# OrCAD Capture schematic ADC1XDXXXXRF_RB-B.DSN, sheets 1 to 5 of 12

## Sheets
1 Title Page
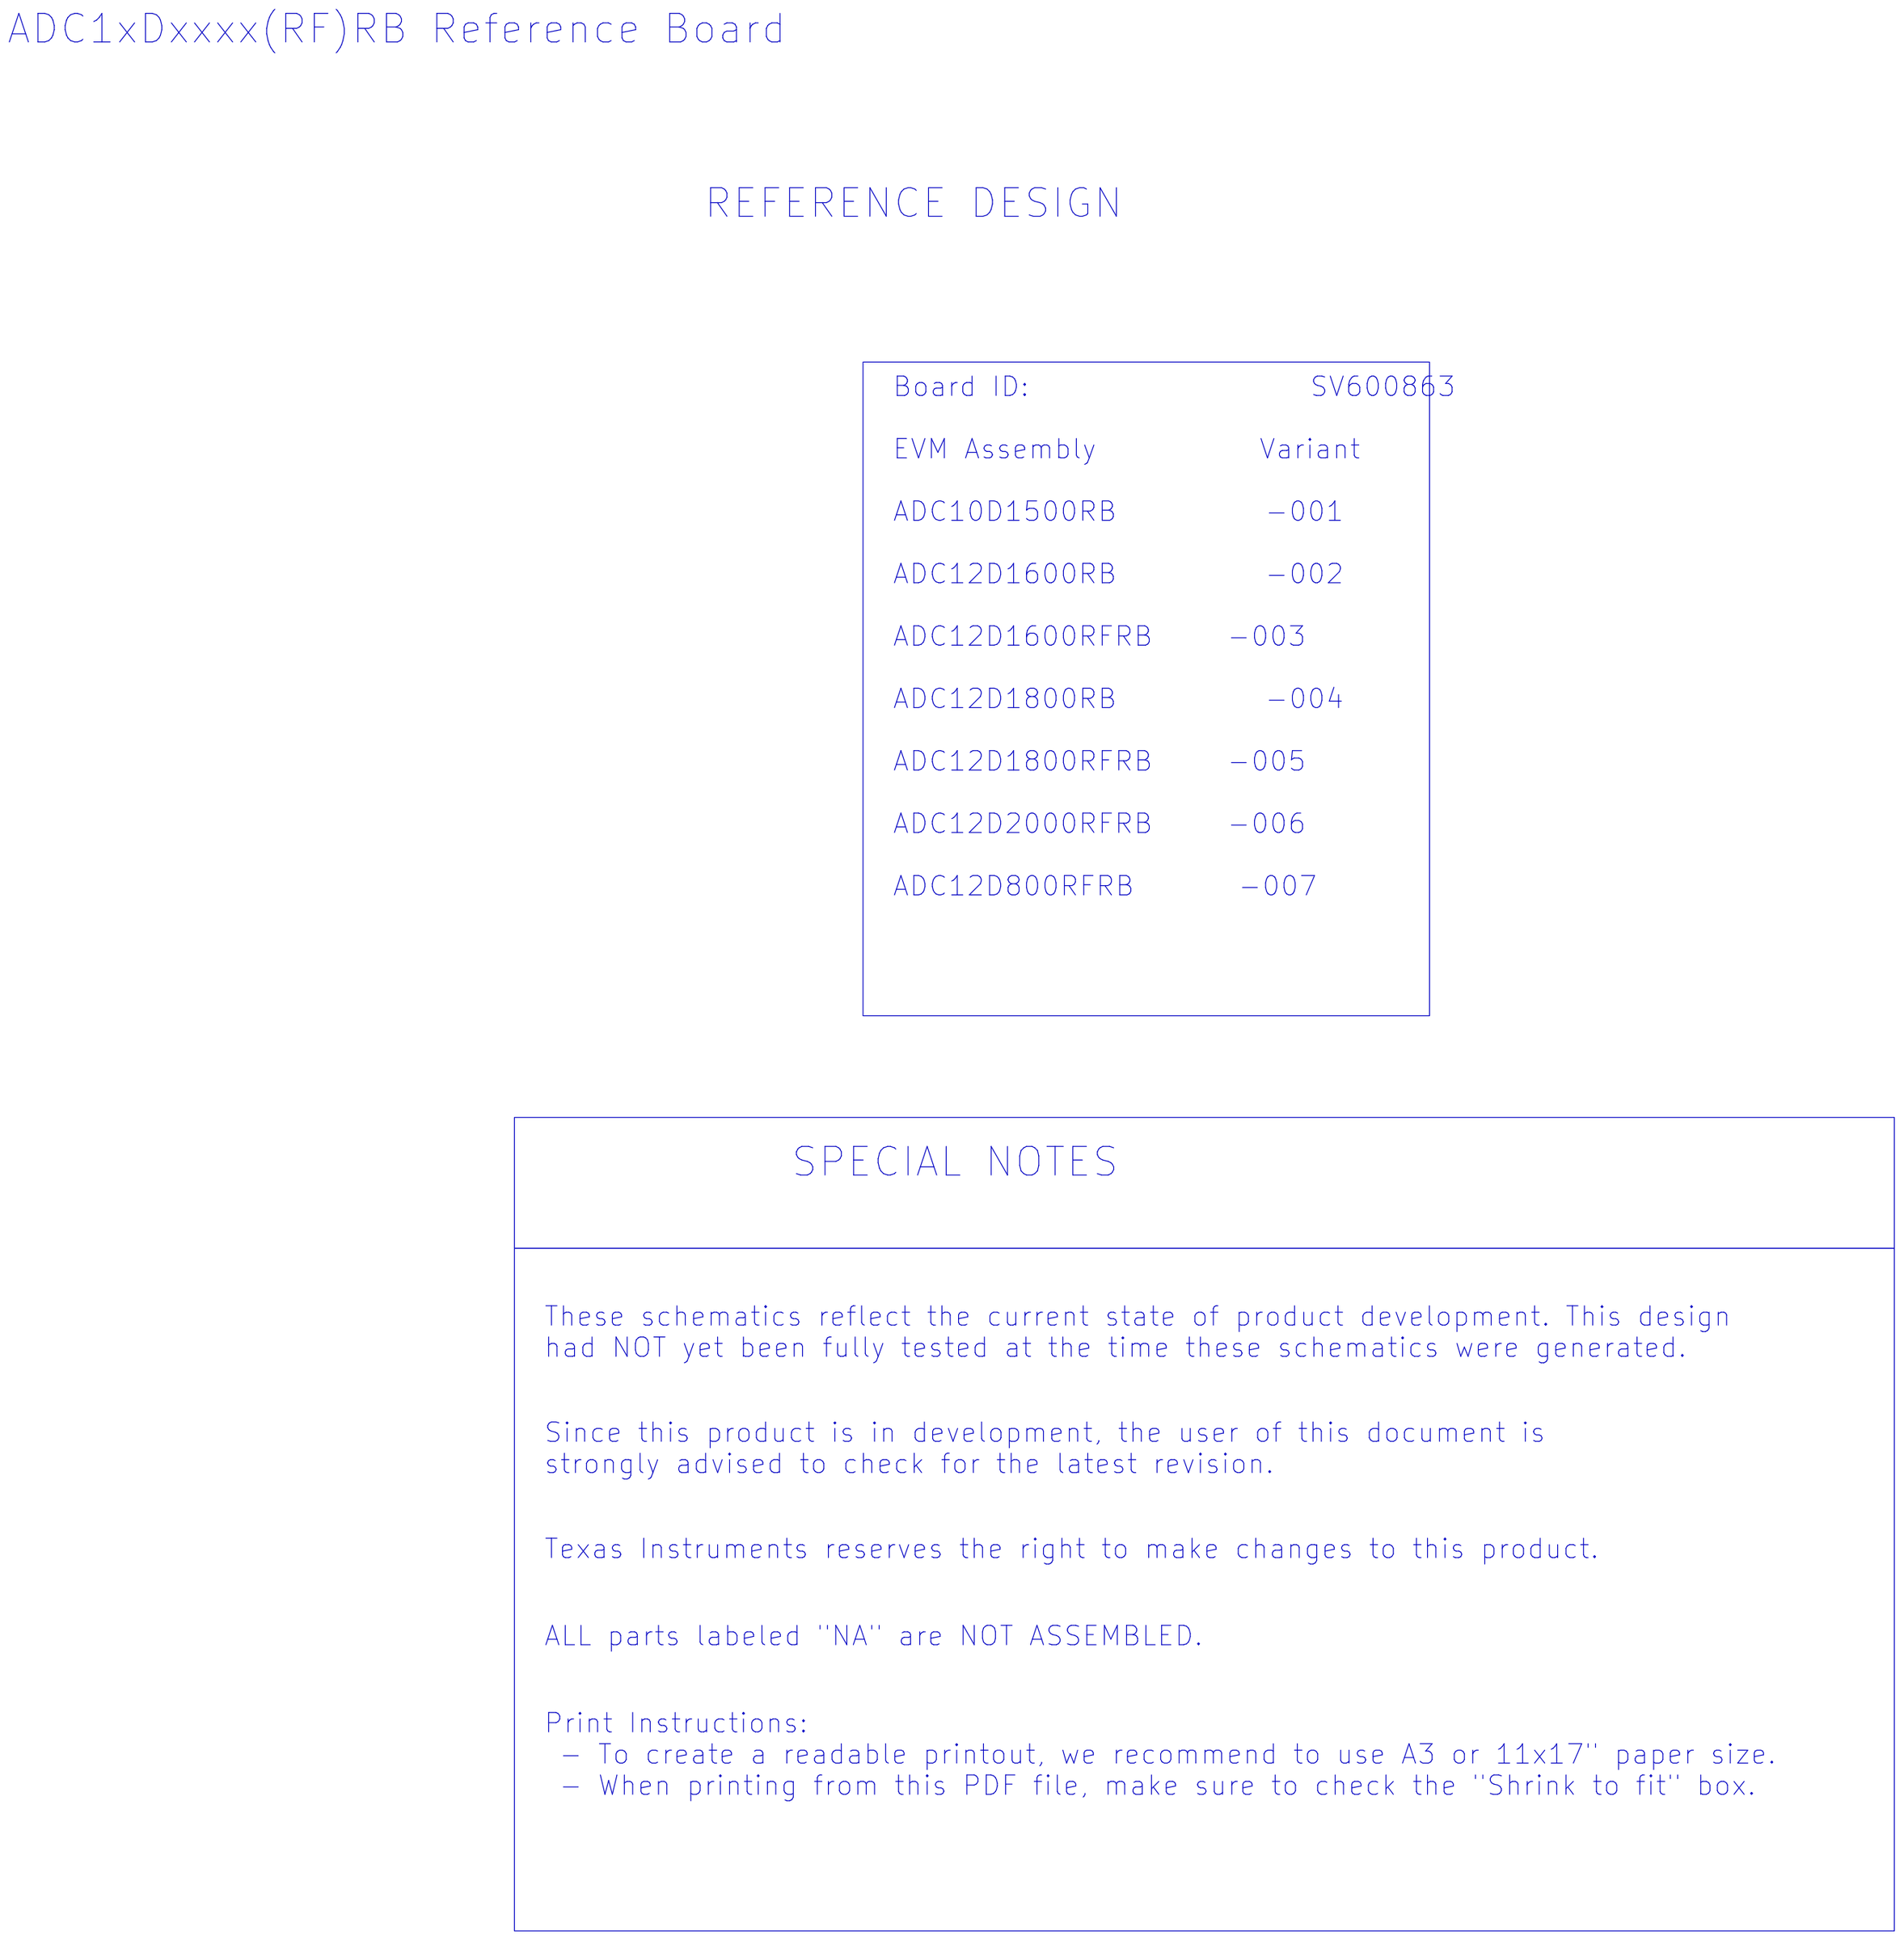
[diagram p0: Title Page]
2 TopBlock: size C
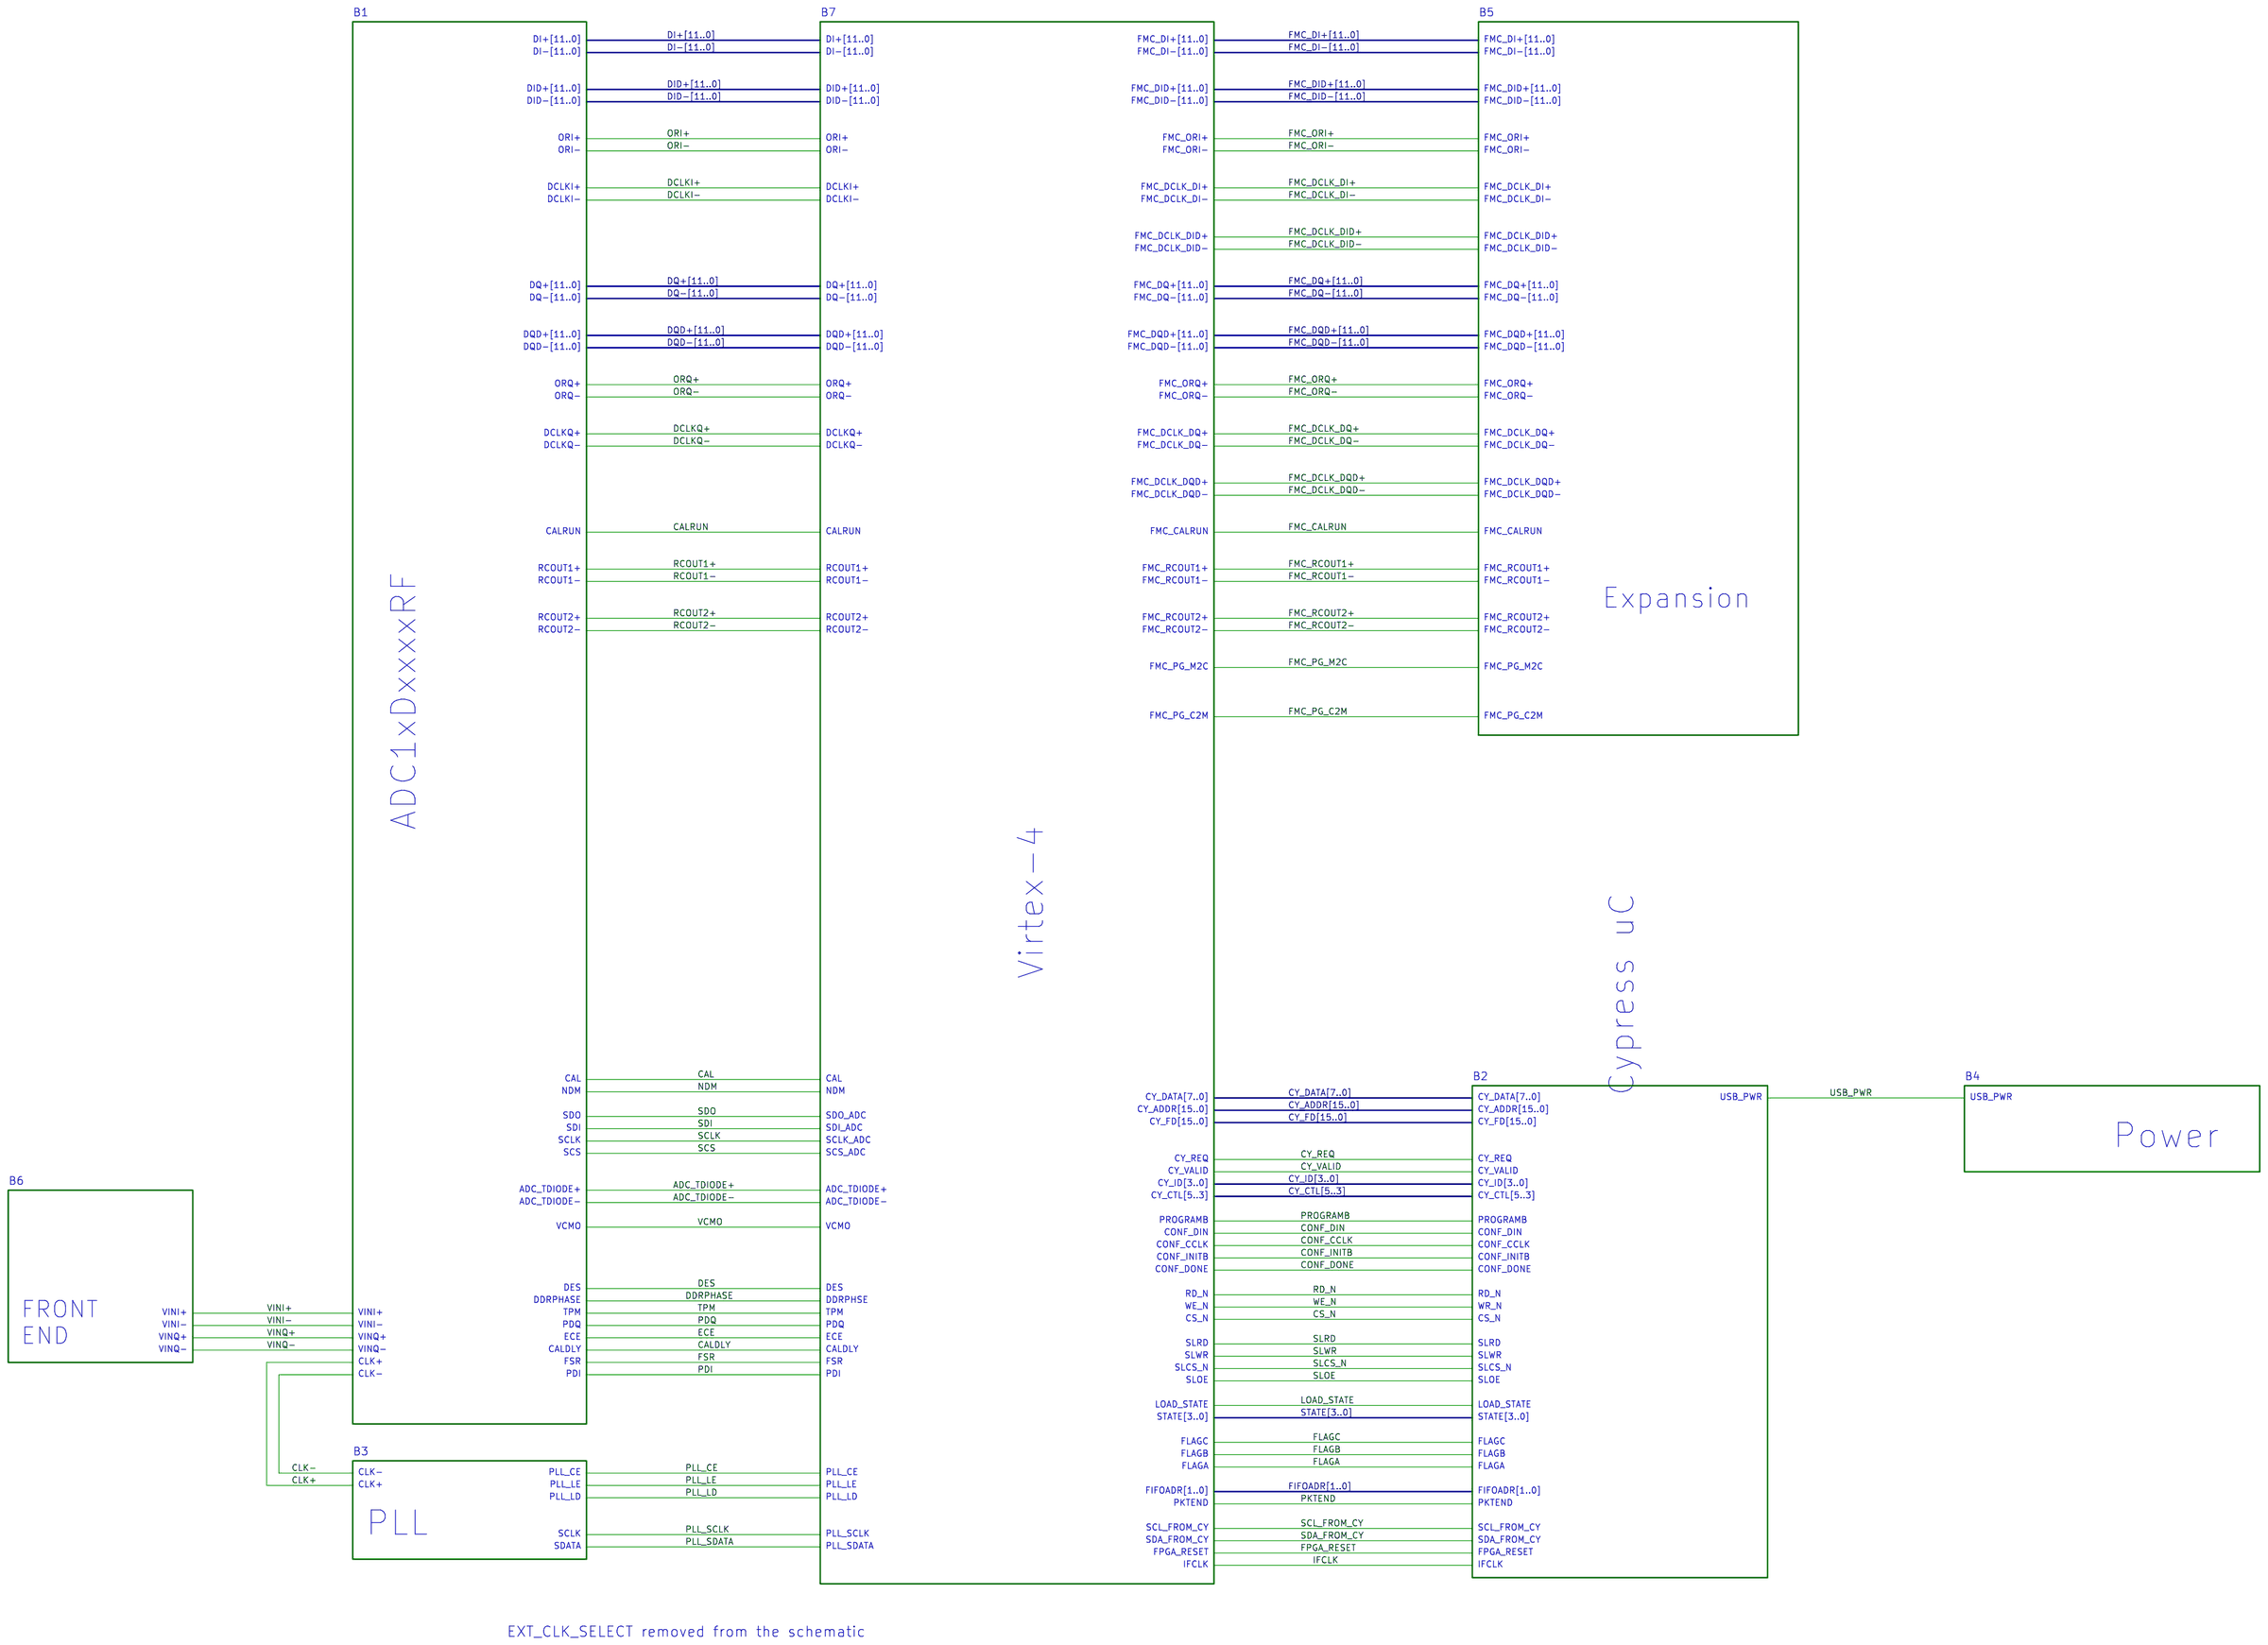
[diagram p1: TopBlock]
3 ADC1xDxxxxRF: size C; block B1
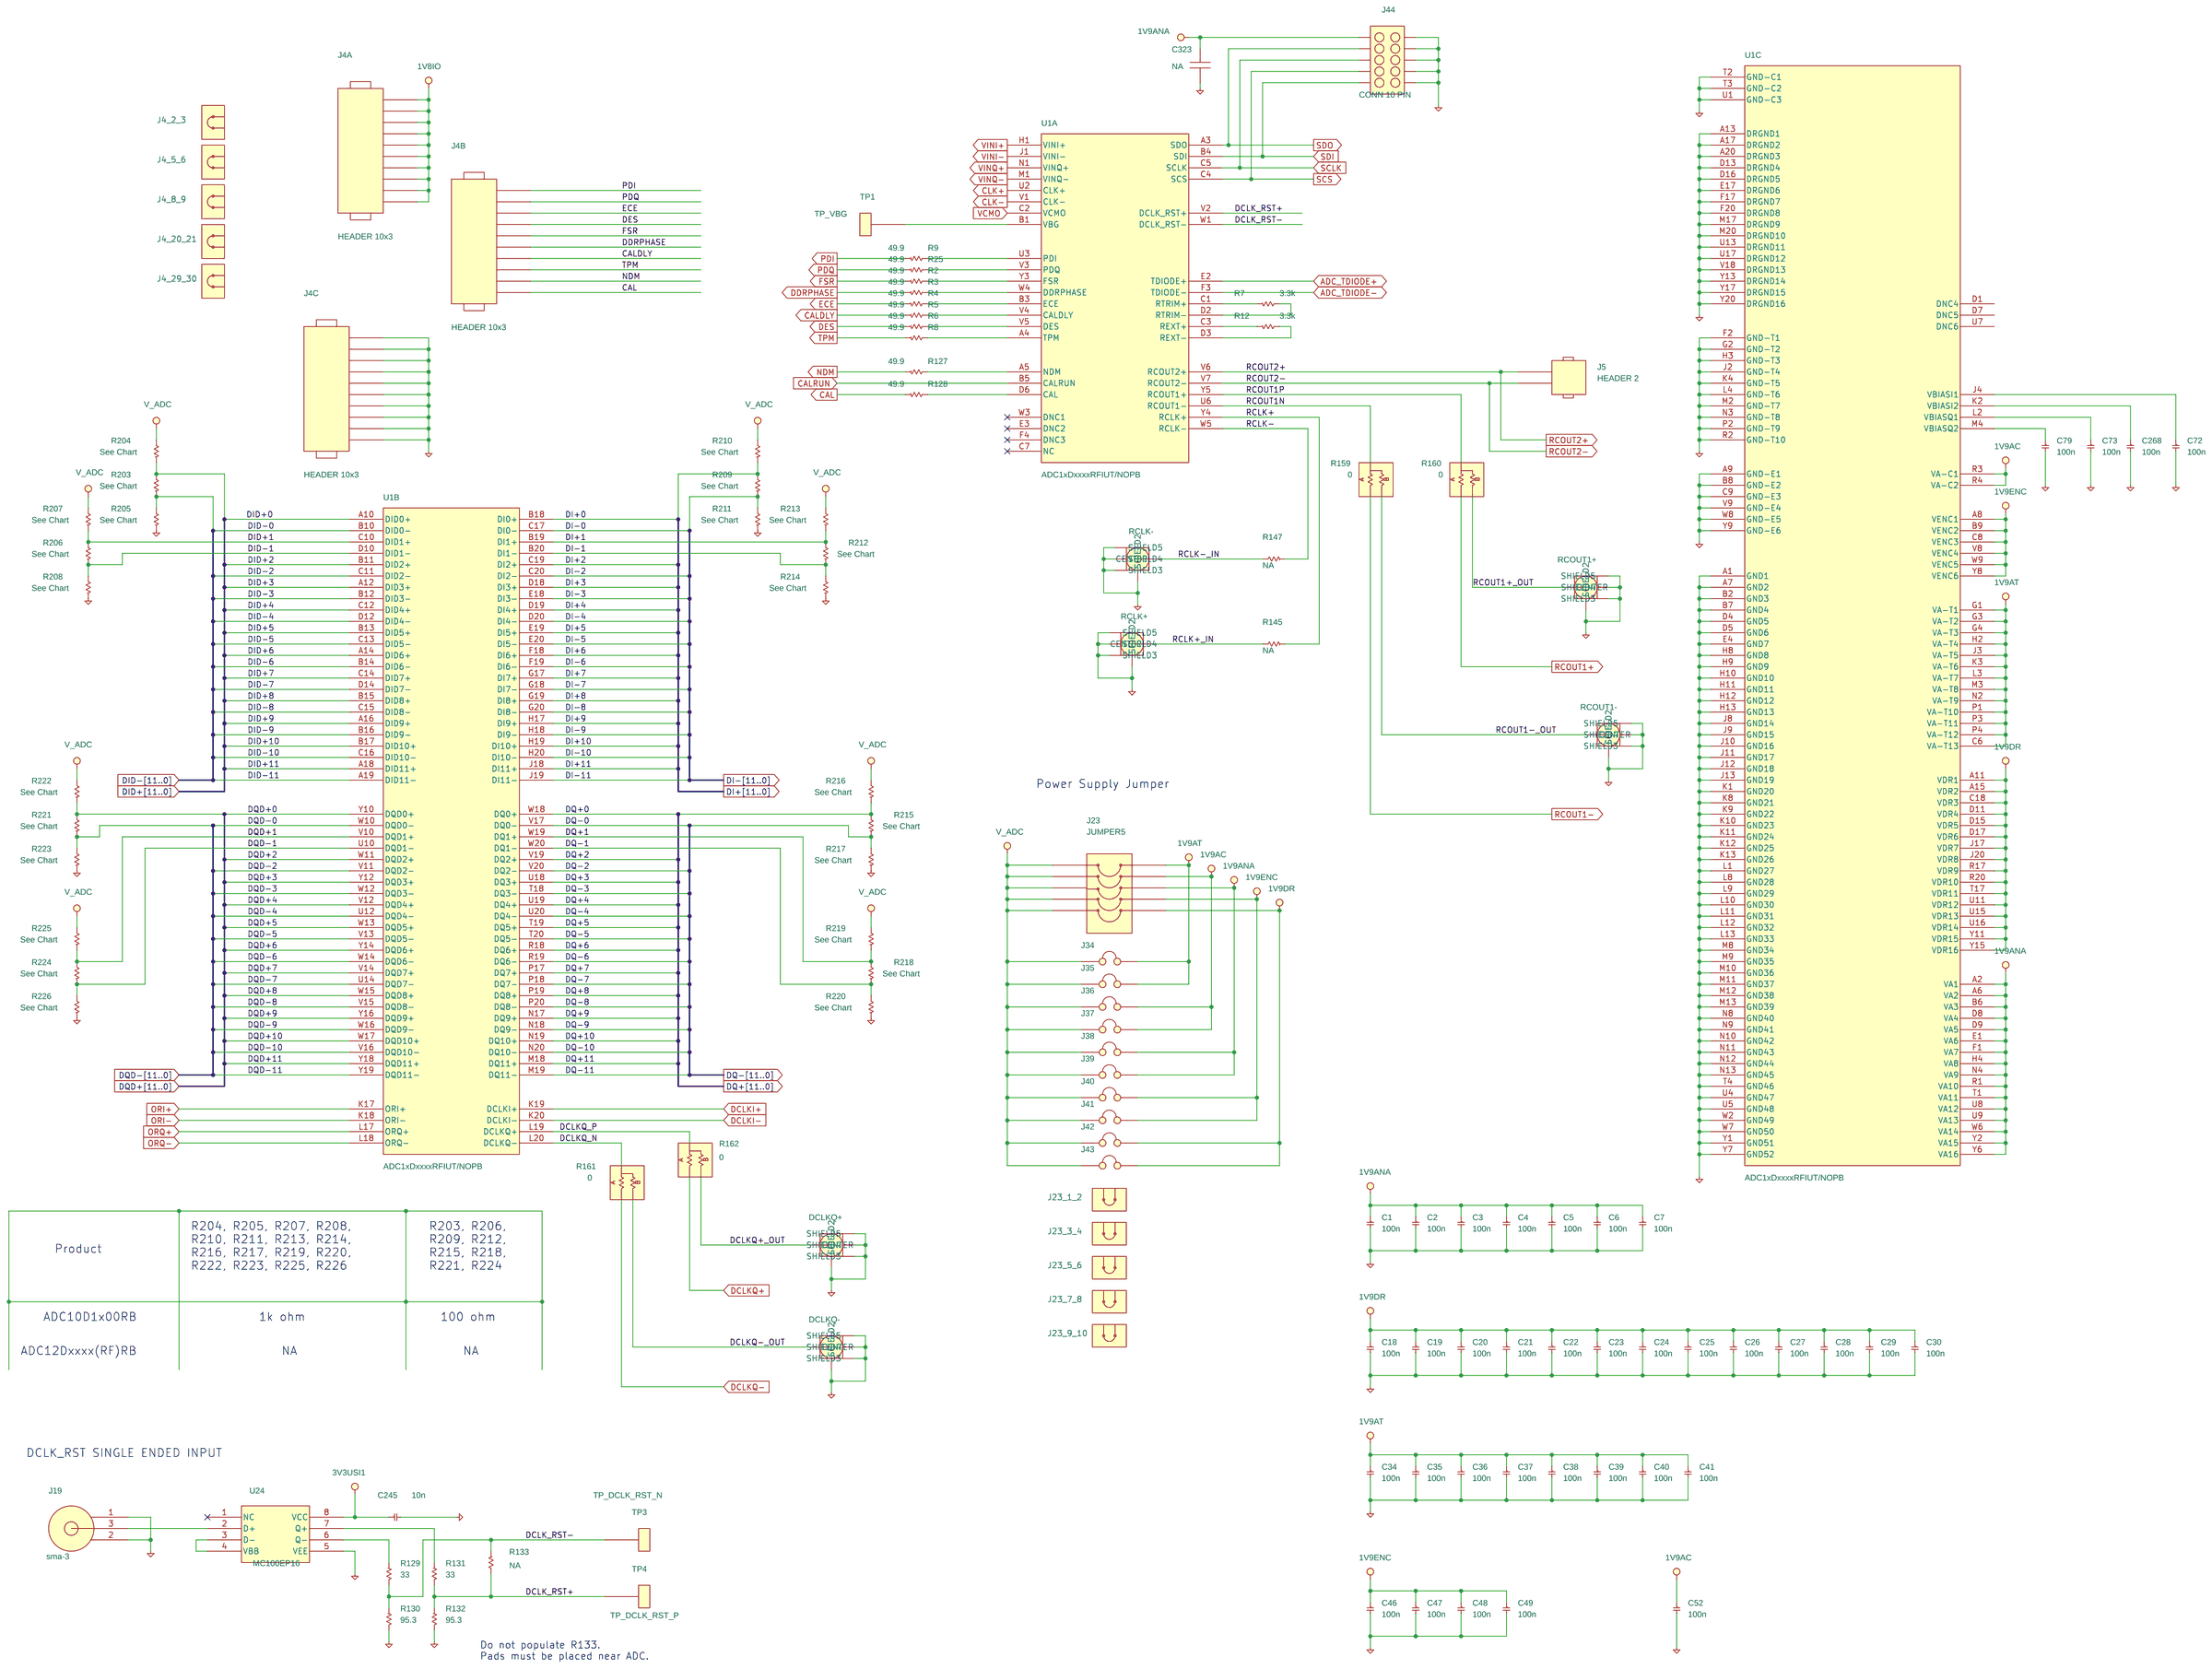
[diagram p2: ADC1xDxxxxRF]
4 Expansion: size C; block B5
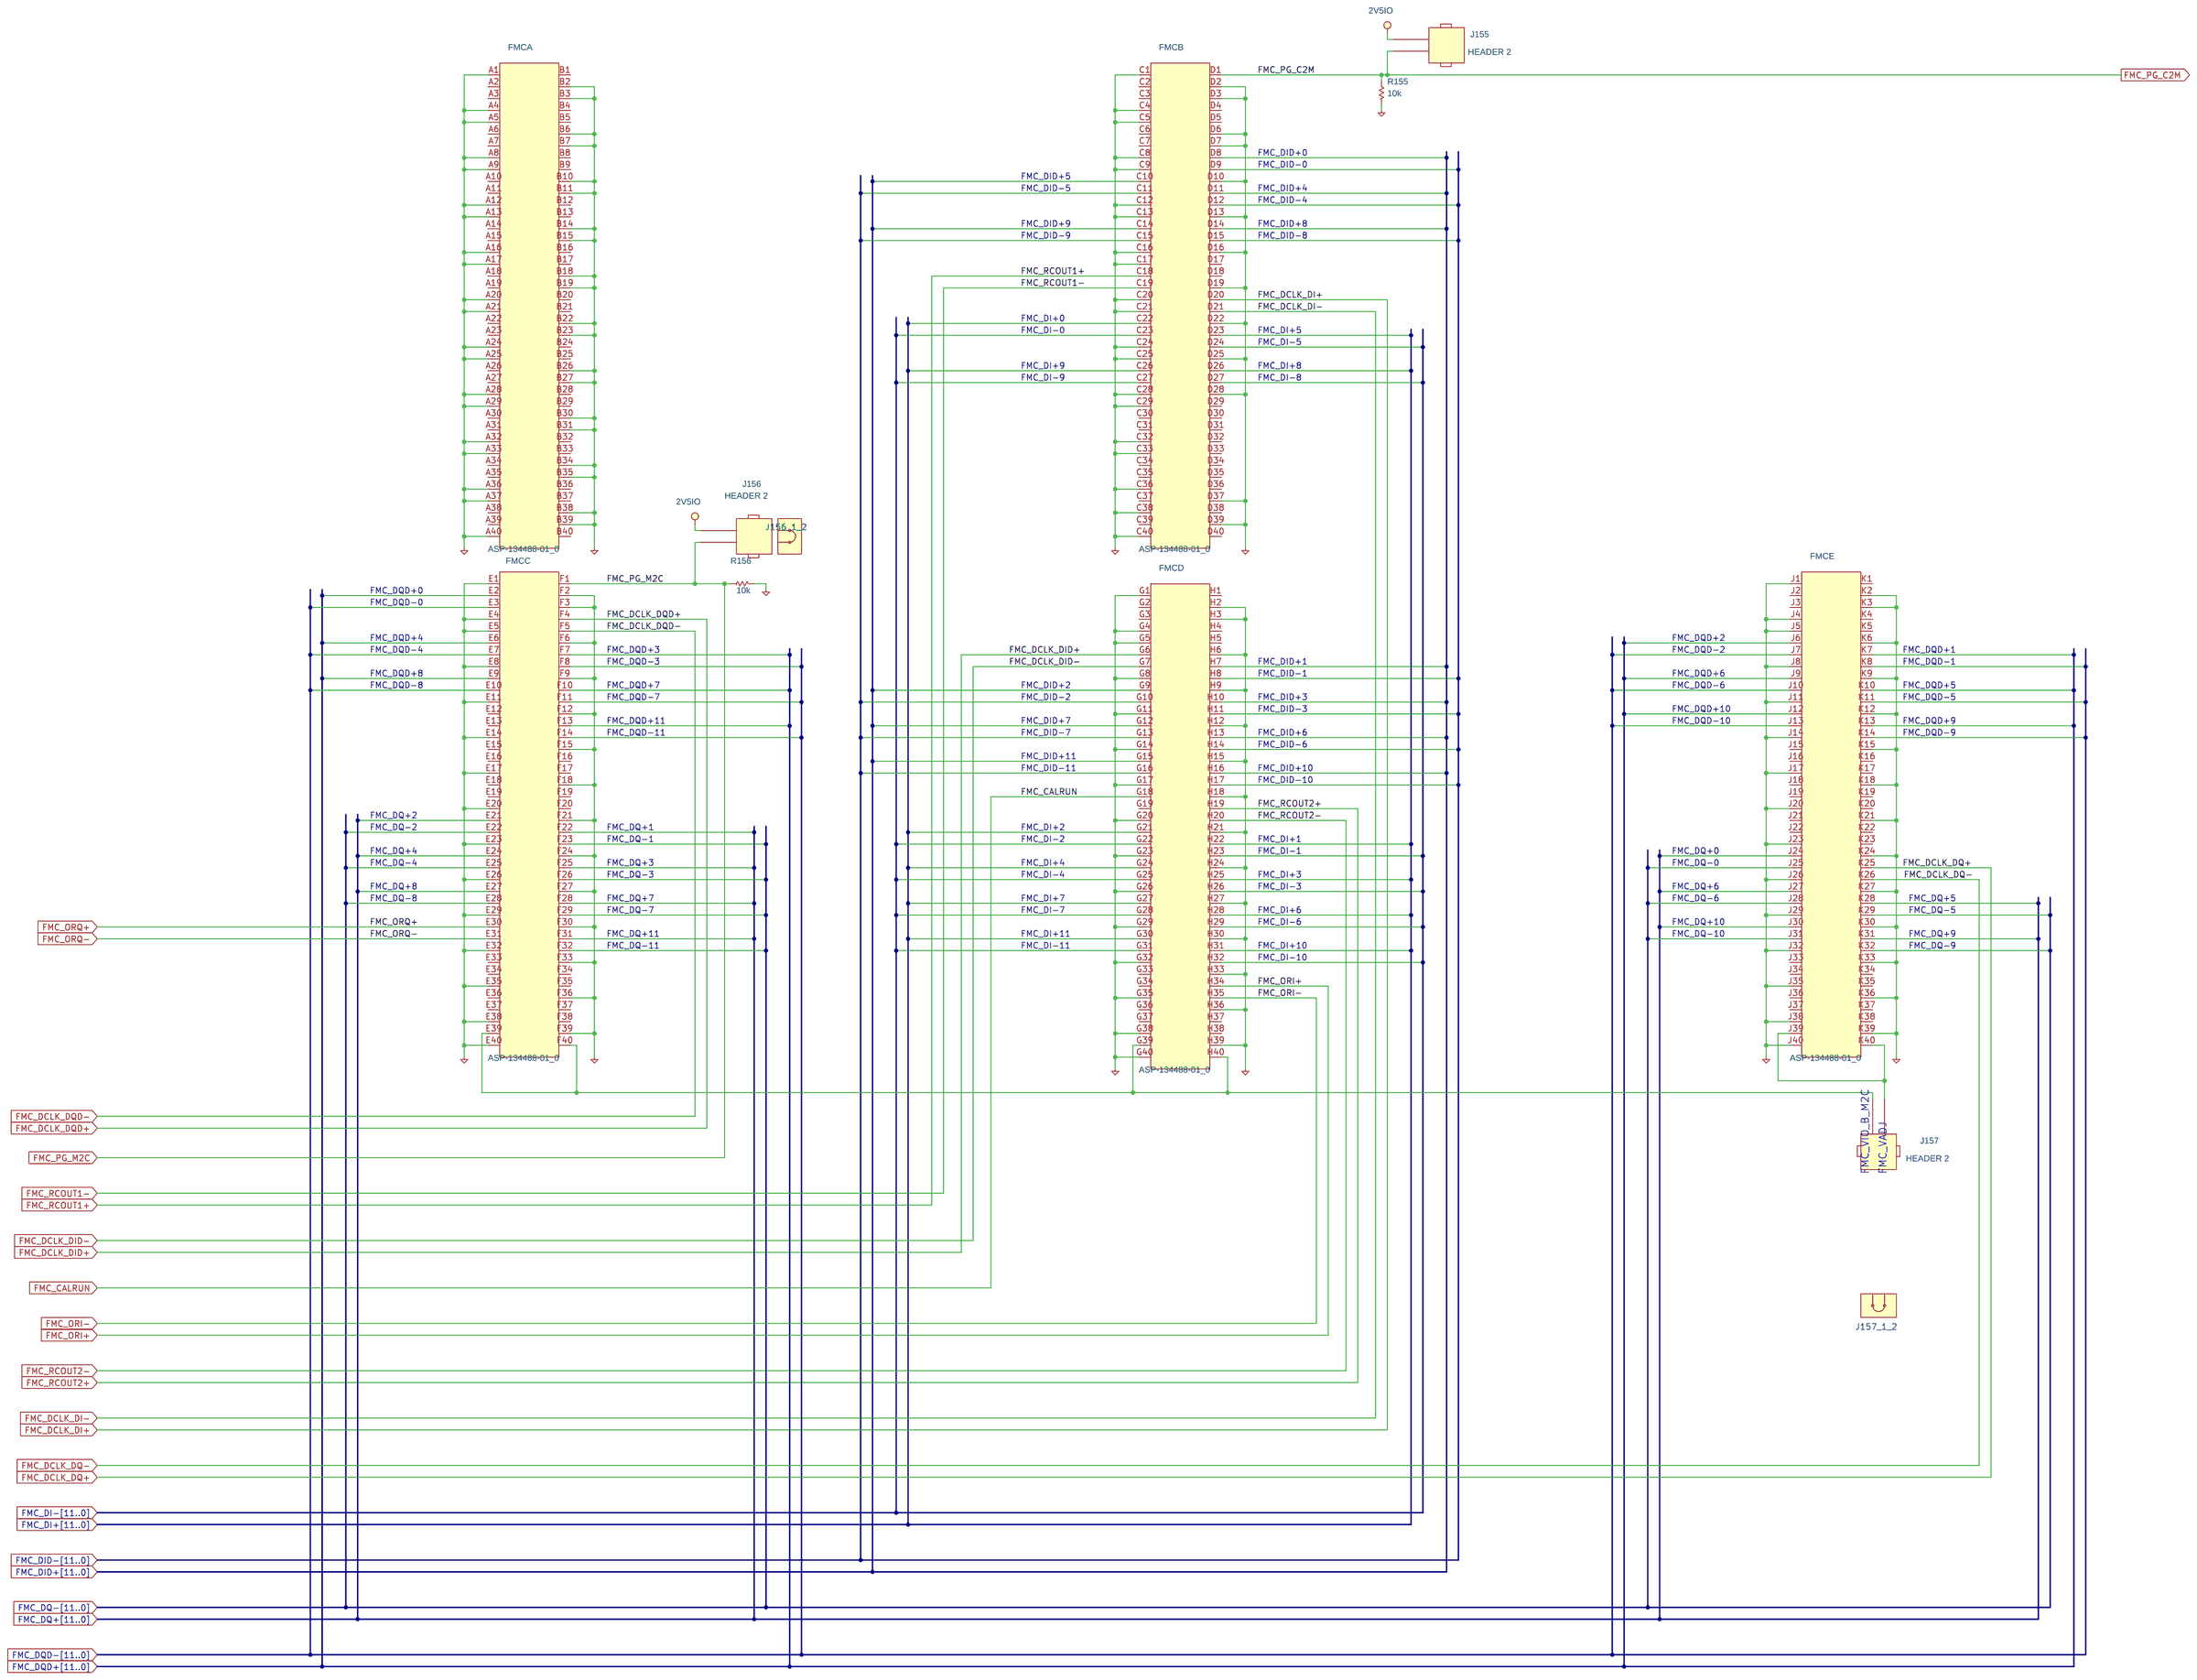
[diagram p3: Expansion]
5 Cypress: size C; block B2
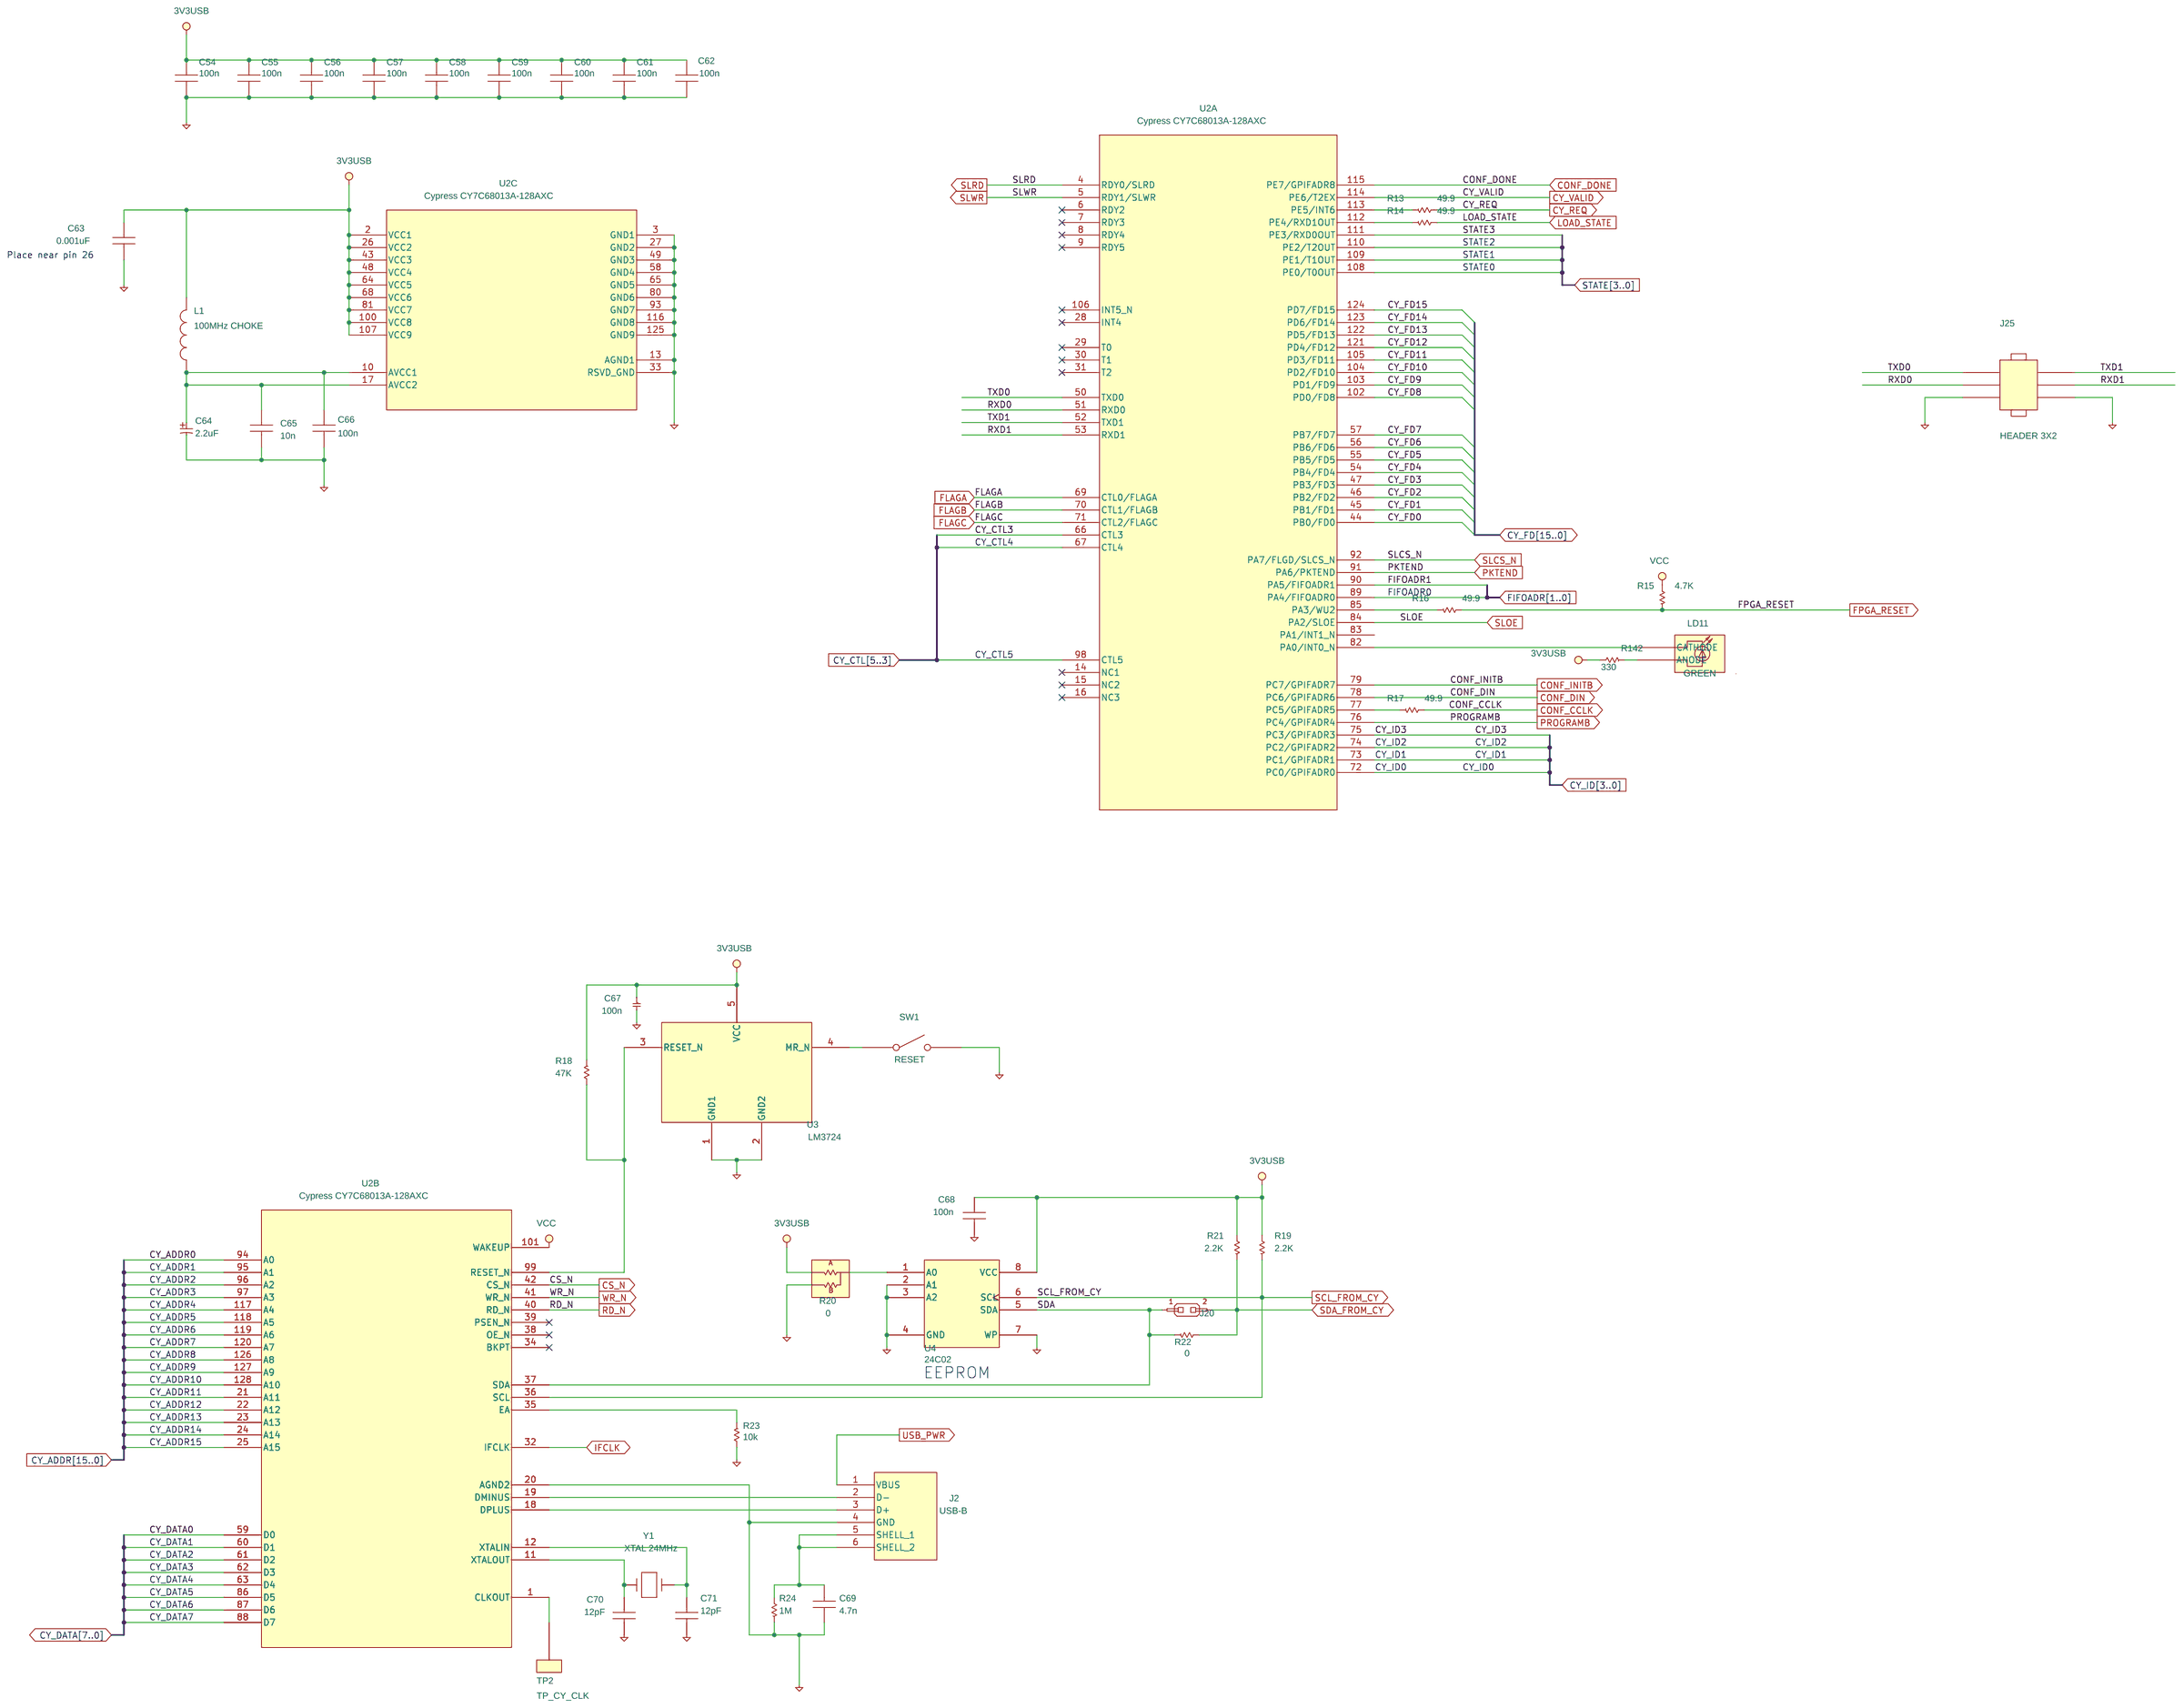
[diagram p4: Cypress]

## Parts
sheet ADC1xDxxxxRF
C1  100n  [c0402]
C2  100n  [c0402]
C3  100n  [c0402]
C4  100n  [c0402]
C5  100n  [c0402]
C6  100n  [c0402]
C7  100n  [c0402]
C18  100n  [c0402]
C19  100n  [c0402]
C20  100n  [c0402]
C21  100n  [c0402]
C22  100n  [c0402]
C23  100n  [c0402]
C24  100n  [c0402]
C25  100n  [c0402_no_ss]
C26  100n  [c0402]
C27  100n  [c0402]
C28  100n  [c0402]
C29  100n  [c0402]
C30  100n  [c0402]
C34  100n  [c0402]
C35  100n  [c0402]
C36  100n  [c0402]
C37  100n  [c0402]
C38  100n  [c0402]
C39  100n  [c0402]
C40  100n  [c0402]
C41  100n  [c0402]
C46  100n  [c0402_no_ss]
C47  100n  [c0402]
C48  100n  [c0402]
C49  100n  [c0402_no_ss]
C52  100n  [c0402]
C72  100n  [c0402]
C73  100n  [c0402]
C79  100n  [c0402]
C245  10n  [c0402]
C268  100n  [c0402]
C323  NA  [c0603]
DCLKQ+  SMA_CONN_2  [SMA_V_CLR]
DCLKQ-  SMA_CONN_2  [SMA_V_CLR]
J4  HEADER 10x3  [blkcon_10x3]  (sections A,B,C)
J4_2_3  SHUNT
J4_5_6  SHUNT
J4_8_9  SHUNT
J4_20_21  SHUNT
J4_29_30  SHUNT
J5  HEADER 2  [BLKCON_2X1]
J19  sma-3  [RF_SMA_END_LAUNCH]
J23  JUMPER5  [blkcon_5x2]
J23_1_2  SHUNT
J23_3_4  SHUNT
J23_5_6  SHUNT
J23_7_8  SHUNT
J23_9_10  SHUNT
J34  jumper/sm/small  [sm_jumper]
J35  jumper/sm/small  [sm_jumper]
J36  jumper/sm/small  [sm_jumper]
J37  jumper/sm/small  [sm_jumper]
J38  jumper/sm/small  [sm_jumper]
J39  jumper/sm/small  [sm_jumper]
J40  jumper/sm/small  [sm_jumper]
J41  jumper/sm/small  [sm_jumper]
J42  jumper/sm/small  [sm_jumper]
J43  jumper/sm/small  [sm_jumper]
J44  CONN 10 PIN  [th_10_hdr2x5_m_str_100]
R2  49.9  [r0603]
R3  49.9  [r0603]
R4  49.9  [r0603]
R5  49.9  [r0603]
R6  49.9  [r0603]
R7  3.3k  [r0603]
R8  49.9  [r0603]
R9  49.9  [r0603]
R12  3.3k  [r0603]
R25  49.9  [r0603]
R127  49.9  [r0603]
R128  49.9  [r0603]
R129  33  [r0603]
R130  95.3  [r0603]
R131  33  [r0603]
R132  95.3  [r0603]
R133  NA  [r0603]
R145  NA  [r0402_no_ss]
R147  NA  [r0402_no_ss]
R159  0  [0402_TRIPAD_1_to_2]
R160  0  [0402_TRIPAD_1_to_2]
R161  0  [0402_TRIPAD_1_to_2]
R162  0  [0402_TRIPAD_1_to_2]
R203  See Chart  [r0402_no_ss]
R204  See Chart  [r0402_no_ss]
R205  See Chart  [r0402_no_ss]
R206  See Chart  [r0402_no_ss]
R207  See Chart  [r0402_no_ss]
R208  See Chart  [r0402_no_ss]
R209  See Chart  [r0402_no_ss]
R210  See Chart  [r0402_no_ss]
R211  See Chart  [r0402_no_ss]
R212  See Chart  [r0402_no_ss]
R213  See Chart  [r0402_no_ss]
R214  See Chart  [r0402_no_ss]
R215  See Chart  [r0402_no_ss]
R216  See Chart  [r0402_no_ss]
R217  See Chart  [r0402_no_ss]
R218  See Chart  [r0402_no_ss]
R219  See Chart  [r0402_no_ss]
R220  See Chart  [r0402_no_ss]
R221  See Chart  [r0402_no_ss]
R222  See Chart  [r0402_no_ss]
R223  See Chart  [r0402_no_ss]
R224  See Chart  [r0402_no_ss]
R225  See Chart  [r0402_no_ss]
R226  See Chart  [r0402_no_ss]
RCLK+  SMA_CONN_2  [SMA_V_CLR]
RCLK-  SMA_CONN_2  [SMA_V_CLR]
RCOUT1+  SMA_CONN_2  [SMA_V_CLR]
RCOUT1-  SMA_CONN_2  [SMA_V_CLR]
TP1  TP_VBG  [tp_smd_s35x28]
TP3  TP_DCLK_RST_N  [tp_smd_s35x28]
TP4  TP_DCLK_RST_P  [tp_smd_s35x28]
U1  ADC1xDxxxxRFIUT/NOPB  [SOCKET_BGA_05_292_B025]  (sections A,B,C)
U24  MC100EP16  [TSSOP8_65M_WG4P9_L3]
sheet Cypress
C54  100n  [c0402]
C55  100n  [c0402]
C56  100n  [c0402]
C57  100n  [c0402]
C58  100n  [c0402]
C59  100n  [c0402]
C60  100n  [c0402]
C61  100n  [c0402]
C62  100n  [c0402]
C63  0.001uF  [c0603]
C64  2.2uF  [c3216]
C65  10n  [c0402]
C66  100n  [c0402]
C67  100n  [c0603]
C68  100n  [c0402]
C69  4.7n  [c1206]
C70  12pF  [c1206]
C71  12pF  [c1206]
J2  USB-B  [usb-jack-b]
J20  JUMPER 2X1  [th_2_hdr1x2_m_str_100]
J25  HEADER 3X2  [blkcon_3x2]
L1  100MHz CHOKE  [r1206]
LD11  GREEN  [r1206]
R13  49.9  [r0603]
R14  49.9  [r0603]
R15  4.7K  [r0603]
R16  49.9  [r0603]
R17  49.9  [r0603]
R18  47K  [r1206]
R19  2.2K  [r1206]
R20  0  [0603_TRIPAD_2_to_3]
R21  2.2K  [r1206]
R22  0  [r0603]
R23  10k  [r0603]
R24  1M  [r1206]
R142  330  [r0603]
SW1  RESET  [sw_2p_6x3p5]
TP2  TP_CY_CLK  [tp_smd_s35x28]
U2  Cypress CY7C68013A-128AXC  [128tqfp]  (sections A,B,C)
U3  LM3724  [SOT23-stx]
U4  24C02  [soic8]
Y1  XTAL 24MHz  [hc49us]
sheet Expansion
FMC  ASP-134488-01_0  [conn_SEAM_040]  (sections A,B,C,D,E)
J155  HEADER 2  [BLKCON_2X1]
J156  HEADER 2  [BLKCON_2X1]
J156_1_2  SHUNT
J157  HEADER 2  [BLKCON_2X1]
J157_1_2  SHUNT
R155  10k  [r0603]
R156  10k  [r0603]

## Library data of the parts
C1-C7 C18-C30 C34-C41 C46-C49 C52 C72 C73 C79 C268 = C-NON-POL: Distributed by: Digikey; Distributor Part #: 478-1129-1-ND; Manufactured by: AVX Corporation; Part Description: CAP CER 0.1UF 10% 10V X5R 0402; Part Number: 0402ZD104KAT2A
C245 = C-NON-POL: Distributed by: Digikey; Distributor Part #: 445-1260-1-ND; Manufactured by: TDK Corporation; Part Description: CAP CER 10000PF 25V 10% X7R 0402; Part Number: C1005X7R1E103K
C323 = CAPACITOR_NON-POL
DCLKQ+ DCLKQ- RCLK+ RCLK- RCOUT1+ RCOUT1- = SMA_CONN_2: Comment: Angel Franquez 800 443 3446 ext. 10; Distributed by: Lighthorse Technologies; Distributor Part #: LTI-SASF546-P26-X1; Manufactured by: Lighthorse Technologies; Part Number: LTI-SASF546-P26-X1
J4 = HEADER_10x3
J4_2_3 J4_5_6 J4_8_9 J4_20_21 J4_29_30 J23_1_2 J23_3_4 J23_5_6 J23_7_8 J23_9_10 J156_1_2 J157_1_2 = SHUNT
J5 J155-J157 = HEADER_2: Comment: BROKEN TO SIZE; Distributed by: Digikey; Distributor Part #: S1012E-36-ND; Manufactured by: Sullins Connector Solutions; Part Description: CONN HEADER .100 SINGL STR 36POS; Part Number: PEC36SAAN
J19 = sma-3_0: Distributed by: Digikey; Distributor Part #: J658-ND; Manufactured by: Emerson Network Power Connectivity Solutions; Part Description: CONN JACK END LAUNCH PC GOLD SMA; Part Number: 142-0701-851
J23 = JUMPER5: Comment: BROKEN TO SIZE; Distributed by: Digikey; Distributor Part #: S2012E-36-ND; Manufactured by: Sullins Connector Solutions; Part Description: CONN HEADER .100 DUAL STR 72POS; Part Number: PEC36DAAN
J34-J43 = jumper_sm_small
J44 = CONN_10_PIN_2mm_SMT_DUAL_ROW: Comment: BROKEN TO SIZE; Distributed by: Digikey; Distributor Part #: S2012E-36-ND; Manufactured by: Sullins Connector Solutions; Part Description: CONN HEADER .100 DUAL STR 72POS; Part Number: PEC36DAAN
R2-R6 R8 R9 R13 R14 R16 R17 R25 R127 R128 = RESISTOR: Distributed by: Digikey; Distributor Part #: P49.9HCT-ND; Manufactured by: Panasonic; Part Description: RES 49.9 OHM 1/10W 1% 0603 SMD; Part Number: ERJ-3EKF49R9V
R7 R12 = RESISTOR: Distributed by: Digikey; Distributor Part #: P3.3KYCT-ND; Manufactured by: Panasonic; Part Description: RES 3.3K OHM 1/10W .1% 0603 SMD; Part Number: ERA-3YEB332V
R129 R131 = RESISTOR: Distributed by: Digikey; Distributor Part #: P33GCT-ND; Manufactured by: Panasonic; Part Description: RES 33 OHM 1/10W 5% 0603 SMD; Part Number: ERJ-3GEYJ330V
R130 R132 = RESISTOR: Distributed by: Digikey; Distributor Part #: P95.3HCT-ND; Manufactured by: Panasonic; Part Description: RES 95.3 OHM 1/10W 1% 0603 SMD; Part Number: ERJ-3EKF95R3V
R133 R145 R147 = RESISTOR
R159-R162 = RESISTOR_TRIPAD: Comment: Assembly A position populated; Distributed by: Digikey; Distributor Part #: 541-0.0JCT-ND; Manufactured by: Panasonic; Part Description: RES 0.0 OHM 1/16W 0402 SMD; Part Number: CRCW04020000Z0ED
R203 R206 R209 R212 R215 R218 R221 R224 = RESISTOR: Manufactured by: Panasonic; Part Number: ERJ-2RKF1000X
R204 R205 R207 R208 R210 R211 R213 R214 R216 R217 R219 R220 R222 R223 R225 R226 = RESISTOR: Manufactured by: Panasonic; Part Number: ERJ-2RKF1001X
TP1-TP4 = TEST_POINT: Part Description: TESTPOINT SMT
U1 = ADC12D800RF
U24 = MC10EP16: Distributed by: Digikey; Distributor Part #: MC100EP16DTGOS-ND; Manufactured by: On Semiconductor; Part Description: IC RCVR/DRVR ECL DIFF 5V 8TSSOP; Part Number: MC100EP16DTG
C54-C62 C66 C68 = CAPACITOR_NON-POL: Distributed by: Digikey; Distributor Part #: 478-1129-1-ND; Manufactured by: AVX Corporation; Part Description: CAP CER 0.1UF 10% 10V X5R 0402; Part Number: 0402ZD104KAT2A
C63 = CAPACITOR_NON-POL: Distributed by: Digikey; Distributor Part #: 490-1451-1-ND; Manufactured by: Murata; Part Description: CAP CERAMIC 0.001uF 0603 SMD; Part Number: GRM1885C1H102JA01D
C64 = C-POLARISED: Distributed by: Digikey; Distributor Part #: 399-3690-1-ND; Manufactured by: Kemet; Part Description: CAP TANT 2.2UF 10V 10% 1206; Part Number: T491A225K010AT
C65 = CAPACITOR_NON-POL: Distributed by: Digikey; Distributor Part #: 445-1260-1-ND; Manufactured by: TDK Corporation; Part Description: CAP CER 10000PF 25V 10% X7R 0402; Part Number: C1005X7R1E103K
C67 = C-NON-POL: Distributed by: Digikey; Distributor Part #: 445-1317-1-ND; Manufactured by: TDK Corporation; Part Description: CAP CER 0.1UF 16V 10% X7R 0603; Part Number: C1608X7R1C104K
C69 = CAPACITOR_NON-POL: Distributed by: Digikey; Distributor Part #: 399-1230-1-ND; Manufactured by: Kemet; Part Description: CAP CER 4700PF 50V 10% X7R 1206; Part Number: C1206C472K5RACTU
C70 C71 = CAPACITOR_NON-POL: Distributed by: Digikey; Distributor Part #: 399-1193-1-ND; Manufactured by: Kemet; Part Description: CAP CER 12PF 50V 5% NP0 1206; Part Number: C1206C120J5GACTU
J2 = USB-B_0: COMPFIXED: NO; COMPGROUP: 0; COMPHEIGHT: 0.000; COMPKEY: NO; COMPLOC: [1080.000,430.000]; COMPLOCKED: NO; COMPROT: 0; COMPSIDE: TOP; DECOUPLER: NO; Distributed by: Digikey; Distributor Part #: ED90064-ND; FPLIST: TM/USB_TYPEB; MEMORY: NO; Manufactured by: Mill-Max; Part Description: USB Connector Type B, Single Through Hole; Part Number: 897-43-004-90-000000
J20 = JUMPER_2X1: Comment: BROKEN TO SIZE; Distributed by: Digikey; Distributor Part #: S1012E-36-ND; Manufactured by: Sullins Connector Solutions; Part Description: CONN HEADER .100 SINGL STR 36POS; Part Number: PEC36SAAN
J25 = HEADER_3X2: Comment: BROKEN TO SIZE; Distributed by: Digikey; Distributor Part #: S2012E-36-ND; Manufactured by: Sullins Connector Solutions; Part Description: CONN HEADER .100 DUAL STR 72POS; Part Number: PEC36DAAN
L1 = CHOKE: Distributed by: Digikey; Distributor Part #: 490-1056-1-ND; Manufactured by: Murata; Part Description: FERRITE CHIP 120 OHM 3000MA 1206; Part Number: BLM31PG121SN1L
LD11 = LED_SNGLE_PANEL: Distributed by: Digikey; Distributor Part #: 67-1357-1-ND; Manufactured by: Lumex; Part Description: LED 565NM WTR CLR GREEN 1206 SMD; Part Number: SML-LX1206GC-TR
R15 = RESISTOR: Distributed by: Digikey; Distributor Part #: P4.7KGCT-ND; Manufactured by: Panasonic; Part Description: RES 4.7K OHM 1/10W 5% 0603 SMD; Part Number: ERJ-3GEYJ472V
R18 = RESISTOR: Distributed by: Digikey; Distributor Part #: P47.0KFCT-ND; Manufactured by: Panasonic; Part Description: RES 47K OHM 1/4W 1% 1206 SMD; Part Number: ERJ-8ENF4702V
R19 R21 = RESISTOR: Distributed by: Digikey; Distributor Part #: P2.2KECT-ND; Manufactured by: Panasonic; Part Description: RES 2.2K OHM 1/10W 5% 1206 SMD; Part Number: ERJ-8GEYJ222V
R20 = RESISTOR_TRIPAD: Distributed by: Digikey; Distributor Part #: P0.0GTR-ND; Manufactured by: Panasonic; Part Description: RES 0 OHM 1/10W 5% 0603 SMD; Part Number: ERJ-3GEY0R00V
R22 = RESISTOR: Distributed by: Digikey; Distributor Part #: P0.0GCT-ND; Manufactured by: Panasonic; Part Description: RES 0 OHM 1/10W 5% 0603 SMD; Part Number: ERJ-3GEY0R00V
R23 R155 R156 = RESISTOR: Distributed by: Digikey; Distributor Part #: P10KGCT-ND; Manufactured by: Panasonic; Part Description: RES 10K OHM 1/10W 5% 0603 SMD; Part Number: ERJ-3GEYJ103V
R24 = RESISTOR: Distributed by: Digikey; Distributor Part #: P1.0MECT-ND; Manufactured by: Panasonic; Part Description: RES 1M OHM 1/10W 5% 1206 SMD; Part Number: ERJ-8GEYJ105V
R142 = RESISTOR: Distributed by: Digikey; Distributor Part #: P330GTR-ND; Manufactured by: Panasonic; Part Description: RES 330 OHM 1/10W 5% 0603 SMD; Part Number: ERJ-3GEYJ331V
SW1 = SW_KEY-SPST: Distributed by: Digikey; Distributor Part #: CKN9017-ND; Manufactured by: ITT Industries/C&K Div; Part Description: SWITCH TACT MOM 130GF H=5MM; Part Number: PTS635SL50
U2 = Cypress_CY7C64613-80NC: Distributed by: Digikey; Distributor Part #: 428-1668-ND; Manufactured by: Cypress; Part Description: IC MCU USB PERIPH HI SPD 128LQFP; Part Number: CY7C68013A-128AXC
U3 = LM3722: Distributed by: Digikey; Distributor Part #: LM3724IM5-3.08CT-ND; Manufactured by: Texas Instruments; Part Description: IC MPU SUPERVISR 3.08V SOT23-5; Part Number: LM3724IM5-3.08/NOPB
U4 = 24C02_SO8_0: Distributed by: Digikey; Distributor Part #: AT24C02BN-10SU-1.8-ND; Manufactured by: Atmel; Part Description: IC SRL EEPROM 2K (256 x 8) 1.8V 8SOIC 2 WIRE; Part Number: AT24C02C-SSHM
Y1 = CRYSTAL: Distributed by: Digikey; Distributor Part #: XC1005-ND; Manufactured by: ECS Inc.; Part Description: CRYSTAL 24.00 MHZ 12PF 49US; Part Number: ECS-240-12-4X
FMC = ASP-134488-01_0: Comment: FMCA, FMCB, FMCC, FMCD and FMCE are only one part so Quantity should only be 1; Distributed by: Digikey; Distributor Part #: SAM8730-ND; Manufactured by: Samtec Inc; Part Description: CONN SNGL-END ARRAY MALE 400POS; Part Number: ASP-134488-01

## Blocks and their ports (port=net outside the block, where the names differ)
B5 = schematic Expansion, on sheet TopBlock: FMC_DCLK_DQ+, FMC_DCLK_DQ-, FMC_ORQ+, FMC_ORQ-, FMC_DI+[11..0], FMC_DI-[11..0], FMC_DCLK_DI-, FMC_DCLK_DI+, FMC_ORI+, FMC_ORI-, FMC_DID+[11..0], FMC_DID-[11..0], FMC_DQ+[11..0], FMC_DQ-[11..0], FMC_DQD+[11..0], FMC_DQD-[11..0], FMC_RCOUT2+, FMC_RCOUT2-, FMC_RCOUT1+, FMC_RCOUT1-, FMC_CALRUN, FMC_PG_M2C, FMC_PG_C2M, FMC_DCLK_DID+, FMC_DCLK_DID-, FMC_DCLK_DQD+, FMC_DCLK_DQD-
B1 = schematic ADC1xDxxxxRF, on sheet TopBlock: VINI+, VINI-, VINQ+, VINQ-, CLK+, CLK-, CAL, VCMO, CALRUN, SDI, SCLK, SDO, ORQ+, ORQ-, ORI+, ORI-, DCLKQ+, DCLKQ-, DCLKI+, DCLKI-, DID+[11..0], DQD+[11..0], DI+[11..0], DQ+[11..0], DID-[11..0], DI-[11..0], DQD-[11..0], DQ-[11..0], ADC_TDIODE+, ADC_TDIODE-, NDM, SCS, PDI, FSR, CALDLY, ECE, PDQ, TPM, DDRPHASE, DES, RCOUT1+, RCOUT1-, RCOUT2-, RCOUT2+
B7 = schematic FPGA, on sheet TopBlock: SCL_FROM_CY, SDA_FROM_CY, ADC_TDIODE+, ADC_TDIODE-, CONF_INITB, PROGRAMB, CONF_CCLK, CONF_DONE, CONF_DIN, CY_CTL[5..3], LOAD_STATE, STATE[3..0], ORQ+, DI-[11..0], ORQ-, DCLKI+, ORI+, DQ-[11..0], DCLKI-, DQD-[11..0], ORI-, DQD+[11..0], DCLKQ+, DI+[11..0], DQ+[11..0], DID-[11..0], DID+[11..0], DCLKQ-, SLCS_N, CY_VALID, CY_ID[3..0], CY_DATA[7..0], FIFOADR[1..0], FPGA_RESET, CY_FD[15..0], SLRD, FLAGA, CS_N, SLWR, FLAGB, WE_N, FLAGC, RD_N, SLOE, CY_REQ, CY_ADDR[15..0], PKTEND, PLL_LD, PLL_SCLK, PLL_LE, PLL_CE, CALRUN, SCS_ADC=SCS, CAL, PLL_SDATA, NDM, SCLK_ADC=SCLK, SDI_ADC=SDI, SDO_ADC=SDO, VCMO, PDI, FSR, CALDLY, ECE, DDRPHSE=DDRPHASE, PDQ, TPM, DES, IFCLK, RCOUT1-, RCOUT1+, FMC_DCLK_DQ+, FMC_DCLK_DQ-, FMC_ORQ+, FMC_ORQ-, FMC_DI+[11..0], FMC_DI-[11..0], FMC_DCLK_DI+, FMC_DCLK_DI-, FMC_ORI+, FMC_ORI-, FMC_DID+[11..0], FMC_DID-[11..0], FMC_DQ+[11..0], FMC_DQ-[11..0], FMC_DQD+[11..0], FMC_DQD-[11..0], RCOUT2+, RCOUT2-, FMC_CALRUN, FMC_RCOUT1+, FMC_RCOUT1-, FMC_RCOUT2+, FMC_RCOUT2-, FMC_PG_M2C, FMC_PG_C2M, FMC_DCLK_DID+, FMC_DCLK_DID-, FMC_DCLK_DQD+, FMC_DCLK_DQD-
B2 = schematic Cypress, on sheet TopBlock: CY_DATA[7..0], USB_PWR, CS_N, WR_N=WE_N, RD_N, FPGA_RESET, SLOE, PKTEND, SLCS_N, LOAD_STATE, CONF_DONE, CY_VALID, CY_REQ, FLAGA, FLAGB, FLAGC, SLRD, SLWR, CONF_INITB, PROGRAMB, CONF_CCLK, SCL_FROM_CY, CY_ADDR[15..0], CY_FD[15..0], CY_ID[3..0], CY_CTL[5..3], STATE[3..0], FIFOADR[1..0], SDA_FROM_CY, CONF_DIN, IFCLK
B6 = schematic Front End, on sheet TopBlock: VINI+, VINI-, VINQ+, VINQ-
B4 = schematic Power, on sheet TopBlock: USB_PWR
B3 = schematic PLL, on sheet TopBlock: SDATA=PLL_SDATA, PLL_LE, PLL_CE, PLL_LD, CLK+, CLK-, SCLK=PLL_SCLK

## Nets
1V8IO: J4.1 J4.4 J4.7 J4.10 J4.13 J4.16 J4.19 J4.22 J4.25 J4.28 ; also on sheet 6 10 11
1V9AC: C52.1 J23.4 J36.2 J37.2 U1.R3(VA-C1) U1.R4(VA-C2)
1V9ANA: C1.1 C2.1 C3.1 C4.1 C5.1 C6.1 C7.1 C323.1 J23.6 J38.2 J39.2 J44.1 U1.A2(VA1) U1.A6(VA2) U1.B6(VA3) U1.D8(VA4) U1.D9(VA5) U1.E1(VA6) U1.F1(VA7) U1.H4(VA8) U1.N4(VA9) U1.R1(VA10) U1.T1(VA11) U1.U8(VA12) U1.U9(VA13) U1.W6(VA14) U1.Y2(VA15) U1.Y6(VA16)
1V9AT: C34.1 C35.1 C36.1 C37.1 C38.1 C39.1 C40.1 C41.1 J23.2 J34.2 J35.2 U1.C6(VA-T13) U1.G1(VA-T1) U1.G3(VA-T2) U1.G4(VA-T3) U1.H2(VA-T4) U1.J3(VA-T5) U1.K3(VA-T6) U1.L3(VA-T7) U1.M3(VA-T8) U1.N2(VA-T9) U1.P1(VA-T10) U1.P3(VA-T11) U1.P4(VA-T12)
1V9DR: C18.1 C19.1 C20.1 C21.1 C22.1 C23.1 C24.1 C25.1 C26.1 C27.1 C28.1 C29.1 C30.1 J23.10 J42.2 J43.2 U1.A11(VDR1) U1.A15(VDR2) U1.C18(VDR3) U1.D11(VDR4) U1.D15(VDR5) U1.D17(VDR6) U1.J17(VDR7) U1.J20(VDR8) U1.R17(VDR9) U1.R20(VDR10) U1.T17(VDR11) U1.U11(VDR12) U1.U15(VDR13) U1.U16(VDR14) U1.Y11(VDR15) U1.Y15(VDR16) ; also on sheet 11
1V9ENC: C46.1 C47.1 C48.1 C49.1 J23.8 J40.2 J41.2 U1.A8(VENC1) U1.B9(VENC2) U1.C8(VENC3) U1.V8(VENC4) U1.W9(VENC5) U1.Y8(VENC6)
2V5IO: J155.2 J156.2 ; also on sheet 6 10 11
3V3USB: C54.1 C55.1 C56.1 C57.1 C58.1 C59.1 C60.1 C61.1 C62.1 C63.1 C67.1 C68.1 L1.2 R15.2 R18.1 R19.2 R20.1 R21.2 R142.2 U2.2(VCC1) U2.26(VCC2) U2.43(VCC3) U2.48(VCC4) U2.64(VCC5) U2.68(VCC6) U2.81(VCC7) U2.100(VCC8) U2.101(WAKEUP) U2.107(VCC9) U3.5(VCC) U4.8(VCC) ; also on sheet 6
3V3USI1: C245.1 U24.8(VCC) ; also on sheet 6 9 10
GND: C1.2 C2.2 C3.2 C4.2 C5.2 C6.2 C7.2 C18.2 C19.2 C20.2 C21.2 C22.2 C23.2 C24.2 C25.2 C26.2 C27.2 C28.2 C29.2 C30.2 C34.2 C35.2 C36.2 C37.2 C38.2 C39.2 C40.2 C41.2 C46.2 C47.2 C48.2 C49.2 C52.2 C54.2 C55.2 C56.2 C57.2 C58.2 C59.2 C60.2 C61.2 C62.2 C63.2 C64.2(NEG) C65.2 C66.2 C67.2 C68.2 C69.1 C70.2 C71.2 C72.2 C73.2 C79.2 C245.2 C268.2 C323.2 DCLKQ+.2(SHIELD2) DCLKQ+.3(SHIELD3) DCLKQ+.4(SHIELD4) DCLKQ+.5(SHIELD5) DCLKQ-.2(SHIELD2) DCLKQ-.3(SHIELD3) DCLKQ-.4(SHIELD4) DCLKQ-.5(SHIELD5) FMC.A1 FMC.A4 FMC.A5 FMC.A8 FMC.A9 FMC.A12 FMC.A13 FMC.A16 FMC.A17 FMC.A20 FMC.A21 FMC.A24 FMC.A25 FMC.A28 FMC.A29 FMC.A32 FMC.A33 FMC.A36 FMC.A37 FMC.A40 FMC.B2 FMC.B3 FMC.B6 FMC.B7 FMC.B10 FMC.B11 FMC.B14 FMC.B15 FMC.B18 FMC.B19 FMC.B22 FMC.B23 FMC.B26 FMC.B27 FMC.B30 FMC.B31 FMC.B34 FMC.B35 FMC.B38 FMC.B39 FMC.C1 FMC.C4 FMC.C5 FMC.C8 FMC.C9 FMC.C12 FMC.C13 FMC.C16 FMC.C17 FMC.C20 FMC.C21 FMC.C24 FMC.C25 FMC.C28 FMC.C29 FMC.C32 FMC.C33 FMC.C36 FMC.C38 FMC.C40 FMC.D2 FMC.D3 FMC.D6 FMC.D7 FMC.D10 FMC.D13 FMC.D16 FMC.D19 FMC.D22 FMC.D25 FMC.D28 FMC.D37 FMC.D39 FMC.E1 FMC.E4 FMC.E5 FMC.E8 FMC.E11 FMC.E14 FMC.E17 FMC.E20 FMC.E23 FMC.E26 FMC.E29 FMC.E32 FMC.E35 FMC.E38 FMC.E40 FMC.F2 FMC.F3 FMC.F6 FMC.F9 FMC.F12 FMC.F15 FMC.F18 FMC.F21 FMC.F24 FMC.F27 FMC.F30 FMC.F33 FMC.F36 FMC.F39 FMC.G1 FMC.G4 FMC.G5 FMC.G8 FMC.G11 FMC.G14 FMC.G17 FMC.G20 FMC.G23 FMC.G26 FMC.G29 FMC.G32 FMC.G35 FMC.G38 FMC.G40 FMC.H2 FMC.H3 FMC.H6 FMC.H9 FMC.H12 FMC.H15 FMC.H18 FMC.H21 FMC.H24 FMC.H27 FMC.H30 FMC.H33 FMC.H36 FMC.H39 FMC.J1 FMC.J4 FMC.J5 FMC.J8 FMC.J11 FMC.J14 FMC.J17 FMC.J20 FMC.J23 FMC.J26 FMC.J29 FMC.J32 FMC.J35 FMC.J38 FMC.J40 FMC.K2 FMC.K3 FMC.K6 FMC.K9 FMC.K12 FMC.K15 FMC.K18 FMC.K21 FMC.K24 FMC.K27 FMC.K30 FMC.K33 FMC.K36 FMC.K39 J2.4(GND) J4.3 J4.6 J4.9 J4.12 J4.15 J4.18 J4.21 J4.24 J4.27 J4.30 J19.1 J19.2 J25.5 J25.6 J44.2 J44.4 J44.6 J44.8 J44.10 R20.3 R23.2 R24.1 R130.2 R132.2 R155.1 R156.2 R205.1 R208.1 R211.1 R214.1 R217.1 R220.1 R223.1 R226.1 RCLK+.2(SHIELD2) RCLK+.3(SHIELD3) RCLK+.4(SHIELD4) RCLK+.5(SHIELD5) RCLK-.2(SHIELD2) RCLK-.3(SHIELD3) RCLK-.4(SHIELD4) RCLK-.5(SHIELD5) RCOUT1+.2(SHIELD2) RCOUT1+.3(SHIELD3) RCOUT1+.4(SHIELD4) RCOUT1+.5(SHIELD5) RCOUT1-.2(SHIELD2) RCOUT1-.3(SHIELD3) RCOUT1-.4(SHIELD4) RCOUT1-.5(SHIELD5) SW1.2 U1.A1(GND1) U1.A7(GND2) U1.A9(GND-E1) U1.A13(DRGND1) U1.A17(DRGND2) U1.A20(DRGND3) U1.B2(GND3) U1.B7(GND4) U1.B8(GND-E2) U1.C9(GND-E3) U1.D4(GND5) U1.D5(GND6) U1.D13(DRGND4) U1.D16(DRGND5) U1.E4(GND7) U1.E17(DRGND6) U1.F2(GND-T1) U1.F17(DRGND7) U1.F20(DRGND8) U1.G2(GND-T2) U1.H3(GND-T3) U1.H8(GND8) U1.H9(GND9) U1.H10(GND10) U1.H11(GND11) U1.H12(GND12) U1.H13(GND13) U1.J2(GND-T4) U1.J8(GND14) U1.J9(GND15) U1.J10(GND16) U1.J11(GND17) U1.J12(GND18) U1.J13(GND19) U1.K1(GND20) U1.K4(GND-T5) U1.K8(GND21) U1.K9(GND22) U1.K10(GND23) U1.K11(GND24) U1.K12(GND25) U1.K13(GND26) U1.L1(GND27) U1.L4(GND-T6) U1.L8(GND28) U1.L9(GND29) U1.L10(GND30) U1.L11(GND31) U1.L12(GND32) U1.L13(GND33) U1.M2(GND-T7) U1.M8(GND34) U1.M9(GND35) U1.M10(GND36) U1.M11(GND37) U1.M12(GND38) U1.M13(GND39) U1.M17(DRGND9) U1.M20(DRGND10) U1.N3(GND-T8) U1.N8(GND40) U1.N9(GND41) U1.N10(GND42) U1.N11(GND43) U1.N12(GND44) U1.N13(GND45) U1.P2(GND-T9) U1.R2(GND-T10) U1.T2(GND-C1) U1.T3(GND-C2) U1.T4(GND46) U1.U1(GND-C3) U1.U4(GND47) U1.U5(GND48) U1.U13(DRGND11) U1.U17(DRGND12) U1.V9(GND-E4) U1.V18(DRGND13) U1.W2(GND49) U1.W7(GND50) U1.W8(GND-E5) U1.Y1(GND51) U1.Y7(GND52) U1.Y9(GND-E6) U1.Y13(DRGND14) U1.Y17(DRGND15) U1.Y20(DRGND16) U2.3(GND1) U2.13(AGND1) U2.20(AGND2) U2.27(GND2) U2.33(RSVD_GND) U2.49(GND3) U2.58(GND4) U2.65(GND5) U2.80(GND6) U2.93(GND7) U2.116(GND8) U2.125(GND9) U3.1(GND1) U3.2(GND2) U4.2(A1) U4.3(A2) U4.4(GND) U4.7(WP) U24.5(VEE) ; also on sheet 6 7 8 9 10 11 12
VINI+: U1.H1(VINI+) ; also on sheet 12
VINI-: U1.J1(VINI-) ; also on sheet 12
VINQ+: U1.N1(VINQ+) ; also on sheet 12
VINQ-: U1.M1(VINQ-) ; also on sheet 12
ADC_TDIODE+: U1.E2(TDIODE+) ; also on sheet 10
ADC_TDIODE-: U1.F3(TDIODE-) ; also on sheet 10
B1/DCLK_RST+: R131.2 R132.1 R133.2 TP4.1 U1.V2(DCLK_RST+)
B1/DCLK_RST-: R129.2 R130.1 R133.1 TP3.1 U1.W1(DCLK_RST-)
B1/DCLKQ+_OUT: DCLKQ+.1(CENTER) R162.3
B1/DCLKQ-_OUT: DCLKQ-.1(CENTER) R161.3
B1/DCLKQ_N: R161.2 U1.L20(DCLKQ-)
B1/DCLKQ_P: R162.2 U1.L19(DCLKQ+)
B1/RCLK+: R145.1 U1.Y4(RCLK+)
B1/RCLK+_IN: R145.2 RCLK+.1(CENTER)
B1/RCLK-: R147.1 U1.W5(RCLK-)
B1/RCLK-_IN: R147.2 RCLK-.1(CENTER)
B1/RCOUT1+_OUT: R160.3 RCOUT1+.1(CENTER)
B1/RCOUT1-_OUT: R159.3 RCOUT1-.1(CENTER)
B1/RCOUT1N: R159.2 U1.U6(RCOUT1-)
B1/RCOUT1P: R160.2 U1.Y5(RCOUT1+)
B2/RXD0: J25.4 U2.51(RXD0)
B2/RXD1: J25.3 U2.53(RXD1)
B2/SDA: J20.1 R22.1 U2.37(SDA) U4.5(SDA)
B2/TXD0: J25.2 U2.50(TXD0)
B2/TXD1: J25.1 U2.52(TXD1)
CAL: J4.29 R128.1 ; also on sheet 9
CALDLY: J4.20 R5.1 ; also on sheet 9
CALRUN: U1.B5(CALRUN) ; also on sheet 9
CLK+: U1.U2(CLK+) ; also on sheet 8
CLK-: U1.V1(CLK-) ; also on sheet 8
CONF_CCLK: R17.2 ; also on sheet 10
CONF_DIN: U2.78(PC6/GPIFADR6) ; also on sheet 10
CONF_DONE: U2.115(PE7/GPIFADR8) ; also on sheet 10
CONF_INITB: U2.79(PC7/GPIFADR7) ; also on sheet 10
CS_N: U2.42(CS_N) ; also on sheet 9
CY_ADDR0: U2.94(A0) ; also on sheet 9
CY_ADDR1: U2.95(A1) ; also on sheet 9
CY_ADDR2: U2.96(A2) ; also on sheet 9
CY_ADDR3: U2.97(A3) ; also on sheet 9
CY_ADDR4: U2.117(A4) ; also on sheet 9
CY_ADDR5: U2.118(A5) ; also on sheet 9
CY_ADDR6: U2.119(A6) ; also on sheet 9
CY_ADDR7: U2.120(A7) ; also on sheet 9
CY_ADDR8: U2.126(A8) ; also on sheet 9
CY_ADDR9: U2.127(A9) ; also on sheet 9
CY_ADDR10: U2.128(A10) ; also on sheet 9
CY_ADDR11: U2.21(A11) ; also on sheet 9
CY_ADDR12: U2.22(A12) ; also on sheet 9
CY_ADDR13: U2.23(A13) ; also on sheet 9
CY_ADDR14: U2.24(A14) ; also on sheet 9
CY_ADDR15: U2.25(A15) ; also on sheet 9
CY_CTL3: U2.66(CTL3) ; also on sheet 10
CY_CTL4: U2.67(CTL4) ; also on sheet 10
CY_CTL5: U2.98(CTL5) ; also on sheet 10
CY_DATA0: U2.59(D0) ; also on sheet 9
CY_DATA1: U2.60(D1) ; also on sheet 9
CY_DATA2: U2.61(D2) ; also on sheet 9
CY_DATA3: U2.62(D3) ; also on sheet 9
CY_DATA4: U2.63(D4) ; also on sheet 9
CY_DATA5: U2.86(D5) ; also on sheet 9
CY_DATA6: U2.87(D6) ; also on sheet 9
CY_DATA7: U2.88(D7) ; also on sheet 9
CY_FD0: U2.44(PB0/FD0) ; also on sheet 9
CY_FD1: U2.45(PB1/FD1) ; also on sheet 9
CY_FD2: U2.46(PB2/FD2) ; also on sheet 9
CY_FD3: U2.47(PB3/FD3) ; also on sheet 9
CY_FD4: U2.54(PB4/FD4) ; also on sheet 9
CY_FD5: U2.55(PB5/FD5) ; also on sheet 9
CY_FD6: U2.56(PB6/FD6) ; also on sheet 9
CY_FD7: U2.57(PB7/FD7) ; also on sheet 9
CY_FD8: U2.102(PD0/FD8) ; also on sheet 9
CY_FD9: U2.103(PD1/FD9) ; also on sheet 9
CY_FD10: U2.104(PD2/FD10) ; also on sheet 9
CY_FD11: U2.105(PD3/FD11) ; also on sheet 9
CY_FD12: U2.121(PD4/FD12) ; also on sheet 9
CY_FD13: U2.122(PD5/FD13) ; also on sheet 9
CY_FD14: U2.123(PD6/FD14) ; also on sheet 9
CY_FD15: U2.124(PD7/FD15) ; also on sheet 9
CY_ID0: U2.72(PC0/GPIFADR0) ; also on sheet 9
CY_ID1: U2.73(PC1/GPIFADR1) ; also on sheet 9
CY_ID2: U2.74(PC2/GPIFADR2) ; also on sheet 9
CY_ID3: U2.75(PC3/GPIFADR3) ; also on sheet 9
CY_REQ: R13.2 ; also on sheet 9
CY_VALID: U2.114(PE6/T2EX) ; also on sheet 9
DCLKI+: U1.K19(DCLKI+) ; also on sheet 9
DCLKI-: U1.K20(DCLKI-) ; also on sheet 9
DCLKQ+: R162.1 ; also on sheet 9
DCLKQ-: R161.1 ; also on sheet 9
DDRPHASE: J4.17 R3.1 ; also on sheet 9
DES: J4.11 R6.1 ; also on sheet 9
DI+0: R209.2 R210.1 U1.B18(DI0+) ; also on sheet 9
DI+1: R212.2 R213.1 U1.B19(DI1+) ; also on sheet 9
DI+2: U1.C19(DI2+) ; also on sheet 9
DI+3: U1.D18(DI3+) ; also on sheet 9
DI+4: U1.D19(DI4+) ; also on sheet 9
DI+5: U1.E19(DI5+) ; also on sheet 9
DI+6: U1.F18(DI6+) ; also on sheet 9
DI+7: U1.G17(DI7+) ; also on sheet 9
DI+8: U1.G19(DI8+) ; also on sheet 9
DI+9: U1.H17(DI9+) ; also on sheet 9
DI+10: U1.H19(DI10+) ; also on sheet 9
DI+11: U1.J18(DI11+) ; also on sheet 9
DI-0: R209.1 R211.2 U1.C17(DI0-) ; also on sheet 9
DI-1: R212.1 R214.2 U1.B20(DI1-) ; also on sheet 9
DI-2: U1.C20(DI2-) ; also on sheet 9
DI-3: U1.E18(DI3-) ; also on sheet 9
DI-4: U1.D20(DI4-) ; also on sheet 9
DI-5: U1.E20(DI5-) ; also on sheet 9
DI-6: U1.F19(DI6-) ; also on sheet 9
DI-7: U1.G18(DI7-) ; also on sheet 9
DI-8: U1.G20(DI8-) ; also on sheet 9
DI-9: U1.H18(DI9-) ; also on sheet 9
DI-10: U1.H20(DI10-) ; also on sheet 9
DI-11: U1.J19(DI11-) ; also on sheet 9
DID+0: R203.2 R204.1 U1.A10(DID0+) ; also on sheet 9
DID+1: R206.2 R207.1 U1.C10(DID1+) ; also on sheet 9
DID+2: U1.B11(DID2+) ; also on sheet 9
DID+3: U1.A12(DID3+) ; also on sheet 9
DID+4: U1.C12(DID4+) ; also on sheet 9
DID+5: U1.B13(DID5+) ; also on sheet 9
DID+6: U1.A14(DID6+) ; also on sheet 9
DID+7: U1.C14(DID7+) ; also on sheet 9
DID+8: U1.B15(DID8+) ; also on sheet 9
DID+9: U1.A16(DID9+) ; also on sheet 9
DID+10: U1.B17(DID10+) ; also on sheet 9
DID+11: U1.A18(DID11+) ; also on sheet 9
DID-0: R203.1 R205.2 U1.B10(DID0-) ; also on sheet 9
DID-1: R206.1 R208.2 U1.D10(DID1-) ; also on sheet 9
DID-2: U1.C11(DID2-) ; also on sheet 9
DID-3: U1.B12(DID3-) ; also on sheet 9
DID-4: U1.D12(DID4-) ; also on sheet 9
DID-5: U1.C13(DID5-) ; also on sheet 9
DID-6: U1.B14(DID6-) ; also on sheet 9
DID-7: U1.D14(DID7-) ; also on sheet 9
DID-8: U1.C15(DID8-) ; also on sheet 9
DID-9: U1.B16(DID9-) ; also on sheet 9
DID-10: U1.C16(DID10-) ; also on sheet 9
DID-11: U1.A19(DID11-) ; also on sheet 9
DQ+0: R215.2 R216.1 U1.W18(DQ0+) ; also on sheet 9
DQ+1: R218.2 R219.1 U1.W19(DQ1+) ; also on sheet 9
DQ+2: U1.V19(DQ2+) ; also on sheet 9
DQ+3: U1.U18(DQ3+) ; also on sheet 9
DQ+4: U1.U19(DQ4+) ; also on sheet 9
DQ+5: U1.T19(DQ5+) ; also on sheet 9
DQ+6: U1.R18(DQ6+) ; also on sheet 9
DQ+7: U1.P17(DQ7+) ; also on sheet 9
DQ+8: U1.P19(DQ8+) ; also on sheet 9
DQ+9: U1.N17(DQ9+) ; also on sheet 9
DQ+10: U1.N19(DQ10+) ; also on sheet 9
DQ+11: U1.M18(DQ11+) ; also on sheet 9
DQ-0: R215.1 R217.2 U1.V17(DQ0-) ; also on sheet 9
DQ-1: R218.1 R220.2 U1.W20(DQ1-) ; also on sheet 9
DQ-2: U1.V20(DQ2-) ; also on sheet 9
DQ-3: U1.T18(DQ3-) ; also on sheet 9
DQ-4: U1.U20(DQ4-) ; also on sheet 9
DQ-5: U1.T20(DQ5-) ; also on sheet 9
DQ-6: U1.R19(DQ6-) ; also on sheet 9
DQ-7: U1.P18(DQ7-) ; also on sheet 9
DQ-8: U1.P20(DQ8-) ; also on sheet 9
DQ-9: U1.N18(DQ9-) ; also on sheet 9
DQ-10: U1.N20(DQ10-) ; also on sheet 9
DQ-11: U1.M19(DQ11-) ; also on sheet 9
DQD+0: R221.2 R222.1 U1.Y10(DQD0+) ; also on sheet 9
DQD+1: R224.2 R225.1 U1.V10(DQD1+) ; also on sheet 9
DQD+2: U1.W11(DQD2+) ; also on sheet 9
DQD+3: U1.Y12(DQD3+) ; also on sheet 9
DQD+4: U1.V12(DQD4+) ; also on sheet 9
DQD+5: U1.W13(DQD5+) ; also on sheet 9
DQD+6: U1.Y14(DQD6+) ; also on sheet 9
DQD+7: U1.V14(DQD7+) ; also on sheet 9
DQD+8: U1.W15(DQD8+) ; also on sheet 9
DQD+9: U1.Y16(DQD9+) ; also on sheet 9
DQD+10: U1.W17(DQD10+) ; also on sheet 9
DQD+11: U1.Y18(DQD11+) ; also on sheet 9
DQD-0: R221.1 R223.2 U1.W10(DQD0-) ; also on sheet 9
DQD-1: R224.1 R226.2 U1.U10(DQD1-) ; also on sheet 9
DQD-2: U1.V11(DQD2-) ; also on sheet 9
DQD-3: U1.W12(DQD3-) ; also on sheet 9
DQD-4: U1.U12(DQD4-) ; also on sheet 9
DQD-5: U1.V13(DQD5-) ; also on sheet 9
DQD-6: U1.W14(DQD6-) ; also on sheet 9
DQD-7: U1.U14(DQD7-) ; also on sheet 9
DQD-8: U1.V15(DQD8-) ; also on sheet 9
DQD-9: U1.W16(DQD9-) ; also on sheet 9
DQD-10: U1.V16(DQD10-) ; also on sheet 9
DQD-11: U1.Y19(DQD11-) ; also on sheet 9
ECE: J4.8 R4.1 ; also on sheet 9
FIFOADR0: U2.89(PA4/FIFOADR0) ; also on sheet 9
FIFOADR1: U2.90(PA5/FIFOADR1) ; also on sheet 9
FLAGA: U2.69(CTL0/FLAGA) ; also on sheet 9
FLAGB: U2.70(CTL1/FLAGB) ; also on sheet 9
FLAGC: U2.71(CTL2/FLAGC) ; also on sheet 9
FMC_CALRUN: FMC.G18 ; also on sheet 9
FMC_DCLK_DI+: FMC.D20 ; also on sheet 10
FMC_DCLK_DI-: FMC.D21 ; also on sheet 10
FMC_DCLK_DID+: FMC.G6 ; also on sheet 10
FMC_DCLK_DID-: FMC.G7 ; also on sheet 10
FMC_DCLK_DQ+: FMC.K25 ; also on sheet 9
FMC_DCLK_DQ-: FMC.K26 ; also on sheet 9
FMC_DCLK_DQD+: FMC.F4 ; also on sheet 9
FMC_DCLK_DQD-: FMC.F5 ; also on sheet 9
FMC_DI+0: FMC.C22 ; also on sheet 10
FMC_DI+1: FMC.H22 ; also on sheet 10
FMC_DI+2: FMC.G21 ; also on sheet 10
FMC_DI+3: FMC.H25 ; also on sheet 10
FMC_DI+4: FMC.G24 ; also on sheet 10
FMC_DI+5: FMC.D23 ; also on sheet 10
FMC_DI+6: FMC.H28 ; also on sheet 10
FMC_DI+7: FMC.G27 ; also on sheet 10
FMC_DI+8: FMC.D26 ; also on sheet 10
FMC_DI+9: FMC.C26 ; also on sheet 10
FMC_DI+10: FMC.H31 ; also on sheet 10
FMC_DI+11: FMC.G30 ; also on sheet 10
FMC_DI-0: FMC.C23 ; also on sheet 10
FMC_DI-1: FMC.H23 ; also on sheet 10
FMC_DI-2: FMC.G22 ; also on sheet 10
FMC_DI-3: FMC.H26 ; also on sheet 10
FMC_DI-4: FMC.G25 ; also on sheet 10
FMC_DI-5: FMC.D24 ; also on sheet 10
FMC_DI-6: FMC.H29 ; also on sheet 10
FMC_DI-7: FMC.G28 ; also on sheet 10
FMC_DI-8: FMC.D27 ; also on sheet 10
FMC_DI-9: FMC.C27 ; also on sheet 10
FMC_DI-10: FMC.H32 ; also on sheet 10
FMC_DI-11: FMC.G31 ; also on sheet 10
FMC_DID+0: FMC.D8 ; also on sheet 10
FMC_DID+1: FMC.H7 ; also on sheet 10
FMC_DID+2: FMC.G9 ; also on sheet 10
FMC_DID+3: FMC.H10 ; also on sheet 10
FMC_DID+4: FMC.D11 ; also on sheet 10
FMC_DID+5: FMC.C10 ; also on sheet 10
FMC_DID+6: FMC.H13 ; also on sheet 10
FMC_DID+7: FMC.G12 ; also on sheet 10
FMC_DID+8: FMC.D14 ; also on sheet 10
FMC_DID+9: FMC.C14 ; also on sheet 10
FMC_DID+10: FMC.H16 ; also on sheet 10
FMC_DID+11: FMC.G15 ; also on sheet 10
FMC_DID-0: FMC.D9 ; also on sheet 10
FMC_DID-1: FMC.H8 ; also on sheet 10
FMC_DID-2: FMC.G10 ; also on sheet 10
FMC_DID-3: FMC.H11 ; also on sheet 10
FMC_DID-4: FMC.D12 ; also on sheet 10
FMC_DID-5: FMC.C11 ; also on sheet 10
FMC_DID-6: FMC.H14 ; also on sheet 10
FMC_DID-7: FMC.G13 ; also on sheet 10
FMC_DID-8: FMC.D15 ; also on sheet 10
FMC_DID-9: FMC.C15 ; also on sheet 10
FMC_DID-10: FMC.H17 ; also on sheet 10
FMC_DID-11: FMC.G16 ; also on sheet 10
FMC_DQ+0: FMC.J24 ; also on sheet 9
FMC_DQ+1: FMC.F22 ; also on sheet 9
FMC_DQ+2: FMC.E21 ; also on sheet 9
FMC_DQ+3: FMC.F25 ; also on sheet 9
FMC_DQ+4: FMC.E24 ; also on sheet 9
FMC_DQ+5: FMC.K28 ; also on sheet 9
FMC_DQ+6: FMC.J27 ; also on sheet 9
FMC_DQ+7: FMC.F28 ; also on sheet 9
FMC_DQ+8: FMC.E27 ; also on sheet 9
FMC_DQ+9: FMC.K31 ; also on sheet 9
FMC_DQ+10: FMC.J30 ; also on sheet 9
FMC_DQ+11: FMC.F31 ; also on sheet 9
FMC_DQ-0: FMC.J25 ; also on sheet 9
FMC_DQ-1: FMC.F23 ; also on sheet 9
FMC_DQ-2: FMC.E22 ; also on sheet 9
FMC_DQ-3: FMC.F26 ; also on sheet 9
FMC_DQ-4: FMC.E25 ; also on sheet 9
FMC_DQ-5: FMC.K29 ; also on sheet 9
FMC_DQ-6: FMC.J28 ; also on sheet 9
FMC_DQ-7: FMC.F29 ; also on sheet 9
FMC_DQ-8: FMC.E28 ; also on sheet 9
FMC_DQ-9: FMC.K32 ; also on sheet 9
FMC_DQ-10: FMC.J31 ; also on sheet 9
FMC_DQ-11: FMC.F32 ; also on sheet 9
FMC_DQD+0: FMC.E2 ; also on sheet 9
FMC_DQD+1: FMC.K7 ; also on sheet 9
FMC_DQD+2: FMC.J6 ; also on sheet 9
FMC_DQD+3: FMC.F7 ; also on sheet 9
FMC_DQD+4: FMC.E6 ; also on sheet 9
FMC_DQD+5: FMC.K10 ; also on sheet 9
FMC_DQD+6: FMC.J9 ; also on sheet 9
FMC_DQD+7: FMC.F10 ; also on sheet 9
FMC_DQD+8: FMC.E9 ; also on sheet 9
FMC_DQD+9: FMC.K13 ; also on sheet 9
FMC_DQD+10: FMC.J12 ; also on sheet 9
FMC_DQD+11: FMC.F13 ; also on sheet 9
FMC_DQD-0: FMC.E3 ; also on sheet 9
FMC_DQD-1: FMC.K8 ; also on sheet 9
FMC_DQD-2: FMC.J7 ; also on sheet 9
FMC_DQD-3: FMC.F8 ; also on sheet 9
FMC_DQD-4: FMC.E7 ; also on sheet 9
FMC_DQD-5: FMC.K11 ; also on sheet 9
FMC_DQD-6: FMC.J10 ; also on sheet 9
FMC_DQD-7: FMC.F11 ; also on sheet 9
FMC_DQD-8: FMC.E10 ; also on sheet 9
FMC_DQD-9: FMC.K14 ; also on sheet 9
FMC_DQD-10: FMC.J13 ; also on sheet 9
FMC_DQD-11: FMC.F14 ; also on sheet 9
FMC_ORI+: FMC.H34 ; also on sheet 10
FMC_ORI-: FMC.H35 ; also on sheet 10
FMC_ORQ+: FMC.E30 ; also on sheet 9
FMC_ORQ-: FMC.E31 ; also on sheet 9
FMC_PG_C2M: FMC.D1 J155.1 R155.2 ; also on sheet 10
FMC_PG_M2C: FMC.F1 J156.1 R156.1 ; also on sheet 10
FMC_RCOUT1+: FMC.C18 ; also on sheet 9
FMC_RCOUT1-: FMC.C19 ; also on sheet 9
FMC_RCOUT2+: FMC.H19 ; also on sheet 9
FMC_RCOUT2-: FMC.H20 ; also on sheet 9
FPGA_RESET: R15.1 R16.2 ; also on sheet 9
FSR: J4.14 R2.1 ; also on sheet 9
IFCLK: U2.32(IFCLK) ; also on sheet 10
LOAD_STATE: R14.2 ; also on sheet 9
NDM: J4.26 R127.1 ; also on sheet 9
ORI+: U1.K17(ORI+) ; also on sheet 9
ORI-: U1.K18(ORI-) ; also on sheet 9
ORQ+: U1.L17(ORQ+) ; also on sheet 9
ORQ-: U1.L18(ORQ-) ; also on sheet 9
PDI: J4.2 R9.1 ; also on sheet 9
PDQ: J4.5 R25.1 ; also on sheet 9
PKTEND: U2.91(PA6/PKTEND) ; also on sheet 9
PROGRAMB: U2.76(PC4/GPIFADR4) ; also on sheet 10
RCOUT1+: R160.1 ; also on sheet 9
RCOUT1-: R159.1 ; also on sheet 9
RCOUT2+: J5.1 U1.V6(RCOUT2+) ; also on sheet 9
RCOUT2-: J5.2 U1.V7(RCOUT2-) ; also on sheet 9
RD_N: U2.40(RD_N) ; also on sheet 9
SCL_FROM_CY: R19.1 U2.36(SCL) U4.6(SCL) ; also on sheet 10
SCLK: J44.5 U1.C5(SCLK) ; also on sheet 9
SCS: J44.7 U1.C4(SCS) ; also on sheet 9
SDA_FROM_CY: J20.2 R21.1 R22.2 ; also on sheet 10
SDI: J44.9 U1.B4(SDI) ; also on sheet 9
SDO: J44.3 U1.A3(SDO) ; also on sheet 9
SLCS_N: U2.92(PA7/FLGD/SLCS_N) ; also on sheet 9
SLOE: U2.84(PA2/SLOE) ; also on sheet 9
SLRD: U2.4(RDY0/SLRD) ; also on sheet 9
SLWR: U2.5(RDY1/SLWR) ; also on sheet 9
STATE0: U2.108(PE0/T0OUT) ; also on sheet 10
STATE1: U2.109(PE1/T1OUT) ; also on sheet 10
STATE2: U2.110(PE2/T2OUT) ; also on sheet 10
STATE3: U2.111(PE3/RXD0OUT) ; also on sheet 10
TPM: J4.23 R8.1 ; also on sheet 9
USB_PWR: J2.1(VBUS) ; also on sheet 6
V_ADC: J23.1 J23.3 J23.5 J23.7 J23.9 J34.1 J35.1 J36.1 J37.1 J38.1 J39.1 J40.1 J41.1 J42.1 J43.1 R204.2 R207.2 R210.2 R213.2 R216.2 R219.2 R222.2 R225.2 ; also on sheet 6 9 11
VCMO: U1.C2(VCMO) ; also on sheet 10
WE_N: U2.41(WR_N) ; also on sheet 9
B1/N17658689: C268.1 U1.K2(VBIASI2)
B1/N17658690: C79.1 U1.M4(VBIASQ2)
B1/N17663170: C73.1 U1.L2(VBIASQ1)
B1/N17675090: C72.1 U1.J4(VBIASI1)
B1/N17676120: TP1.1 U1.B1(VBG)
B1/N17676520: R12.1 U1.C3(REXT+)
B1/N17676524: R12.2 U1.D3(REXT-)
B1/N17676530: R7.1 U1.C1(RTRIM+)
B1/N17676534: R7.2 U1.D2(RTRIM-)
B1/N17846912: R9.2 U1.U3(PDI)
B1/N17848835: R25.2 U1.V3(PDQ)
B1/N17849798: R2.2 U1.Y3(FSR)
B1/N17850762: R3.2 U1.W4(DDRPHASE)
B1/N17851727: R4.2 U1.B3(ECE)
B1/N17852693: R5.2 U1.V4(CALDLY)
B1/N17853660: R6.2 U1.V5(DES)
B1/N17854628: R8.2 U1.A4(TPM)
B1/N19099019: R127.2 U1.A5(NDM)
B1/N19100077: R128.2 U1.D6(CAL)
B1/N19255100: J19.3 U24.2(D+)
B1/N19265006: R131.1 U24.7(Q+)
B1/N19266083: R129.1 U24.6(Q-)
B1/N19380996: U24.3(D-) U24.4(VBB)
B2/N16721567: J2.3(D+) U2.18(DPLUS)
B2/N16721659: J2.2(D-) U2.19(DMINUS)
B2/N16722721: C69.2 J2.5(SHELL_1) J2.6(SHELL_2) R24.2
B2/N16727306: R23.1 U2.35(EA)
B2/N17041129: R18.2 U2.99(RESET_N) U3.3(RESET_N)
B2/N17122999: R20.2 U4.1(A0)
B2/N17127467: R16.1 U2.85(PA3/WU2)
B2/N17138281: C64.1(POS) C65.1 C66.1 L1.1 U2.10(AVCC1) U2.17(AVCC2)
B2/N17237535: LD11.2(CATHODE) U2.82(PA0/INT0_N)
B2/N17238039: LD11.1(ANODE) R142.1
B2/N17383940: C70.1 U2.11(XTALOUT) Y1.1
B2/N17383990: C71.1 U2.12(XTALIN) Y1.2
B2/N17384219: TP2.1 U2.1(CLKOUT)
B2/N17414023: SW1.1 U3.4(MR_N)
B2/N18092594: R13.1 U2.113(PE5/INT6)
B2/N18092628: R14.1 U2.112(PE4/RXD1OUT)
B2/N18102458: R17.1 U2.77(PC5/GPIFADR5)
B5/N18581058: FMC.J39 FMC.K40 J157.1
B5/N18581183: FMC.E39 FMC.F40 FMC.G39 FMC.H40 J157.2

Not connected (* = marked no-connect by the designer): FMC A2 A3 A6 A7 A10 A11 A14 A15 A18 A19 A22 A23 A26 A27 A30 A31 A34 A35 A38 A39 B1 B4 B5 B8 B9 B12 B13 B16 B17 B20 B21 B24 B25 B28 B29 B32 B33 B36 B37 B40 C2 C3 C6 C7 C30 C31 C34 C35 C37 C39 D4 D5 D17 D18 D29 D30 D31 D32 D33 D34 D35 D36 D38 D40 E12 E13 E15 E16 E18 E19 E33 E34 E36 E37 F16 F17 F19 F20 F34 F35 F37 F38 G2 G3 G19 G33 G34 G36 G37 H1 H4 H5 H37 H38 J2 J3 J15 J16 J18 J19 J21 J22 J33 J34 J36 J37 K1 K4 K5 K16 K17 K19 K20 K22 K23 K34 K35 K37 K38; U1 C7(NC)* D1(DNC4) D7(DNC5) E3(DNC2)* F4(DNC3)* U7(DNC6) W3(DNC1)*; U2 6(RDY2)* 7(RDY3)* 8(RDY4)* 9(RDY5)* 14(NC1)* 15(NC2)* 16(NC3)* 28(INT4)* 29(T0)* 30(T1)* 31(T2)* 34(BKPT)* 38(OE_N)* 39(PSEN_N)* 83(PA1/INT1_N) 106(INT5_N)*; U24 1(NC)*

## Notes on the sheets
sheet 1
- ADC1xDxxxx(RF)RB Reference Board
- REFERENCE DESIGN
- Board ID:                   SV600863
  EVM Assembly           Variant
  ADC10D1500RB          -001
  ADC12D1600RB          -002
  ADC12D1600RFRB     -003
  ADC12D1800RB          -004
  ADC12D1800RFRB     -005
  ADC12D2000RFRB     -006
  ADC12D800RFRB       -007
- SPECIAL NOTES
- These schematics reflect the current state of product development. This design
  had NOT yet been fully tested at the time these schematics were generated.
- Since this product is in development, the user of this document is
  strongly advised to check for the latest revision.
- Texas Instruments reserves the right to make changes to this product.
- ALL parts labeled "NA" are NOT ASSEMBLED.
- Print Instructions:
   - To create a readable printout, we recommend to use A3 or 11x17" paper size.
   - When printing from this PDF file, make sure to check the "Shrink to fit" box.
sheet 2
- Expansion
- ADC1xDxxxxRF
- Virtex-4
- Cypress uC
- Power
- FRONT
  END
- PLL
- EXT_CLK_SELECT removed from the schematic
sheet 3
- Power Supply Jumper
- R204, R205, R207, R208,
  R210, R211, R213, R214,
  R216, R217, R219, R220,
  R222, R223, R225, R226
- R203, R206,
  R209, R212,
  R215, R218,
  R221, R224
- Product
- ADC10D1x00RB
- 1k ohm
- 100 ohm
- ADC12Dxxxx(RF)RB
- NA
- NA
- DCLK_RST SINGLE ENDED INPUT
- Do not populate R133.
  Pads must be placed near ADC.
sheet 4
- FMC_VIO_B_M2C
- FMC_VADJ
sheet 5
- Place near pin 26
- EEPROM
